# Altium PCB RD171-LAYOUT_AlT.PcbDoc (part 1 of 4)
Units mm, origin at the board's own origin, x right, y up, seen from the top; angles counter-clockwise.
Board outline 318.5 x 127 mm, 6 copper layers (TOP, Mid-Layer 1, Mid-Layer 2, Mid-Layer 3, Mid-Layer 4, BOTTOM), stack 1.422 mm thick; 473 components, 225 nets, 1188 pads, 1192 vias.
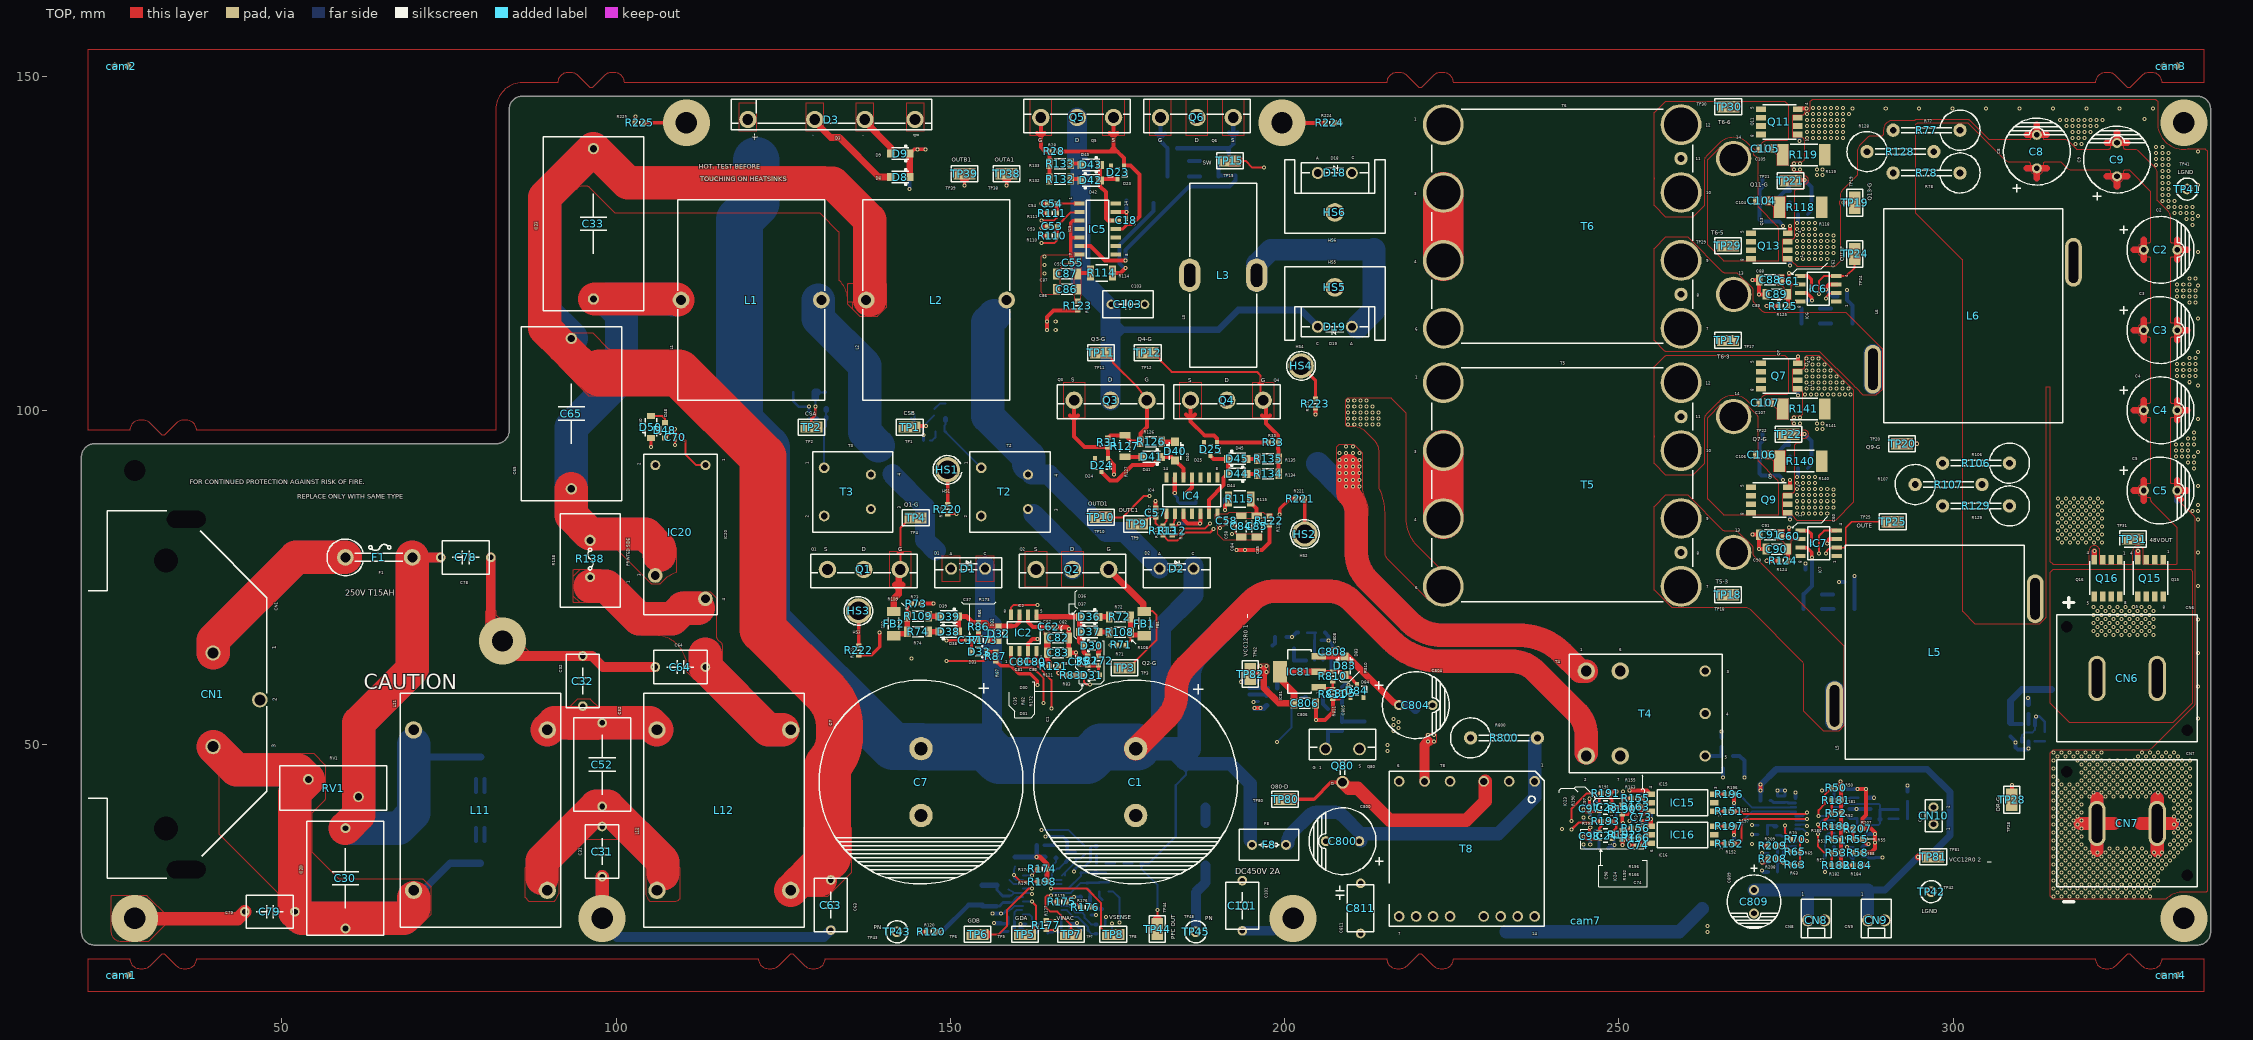
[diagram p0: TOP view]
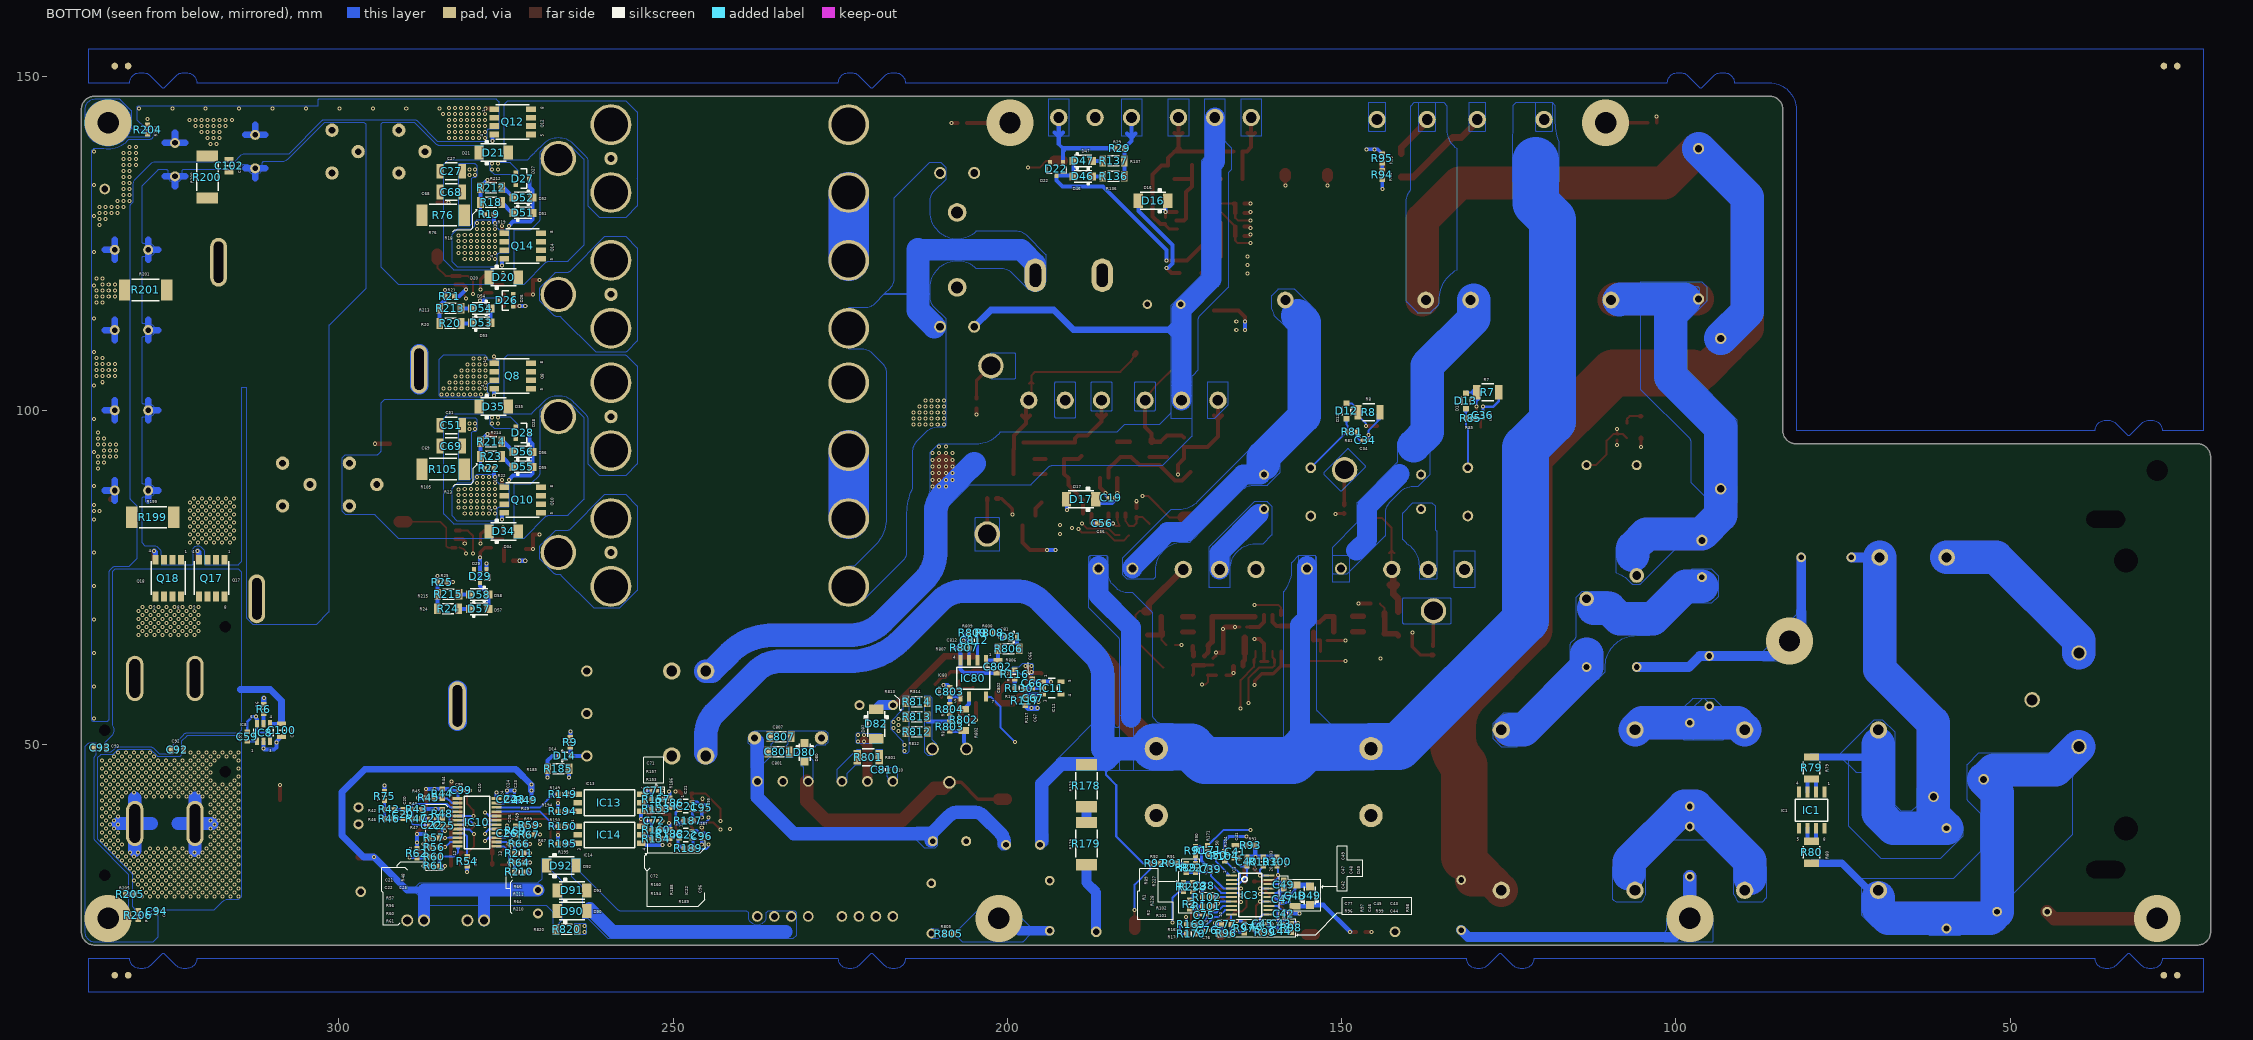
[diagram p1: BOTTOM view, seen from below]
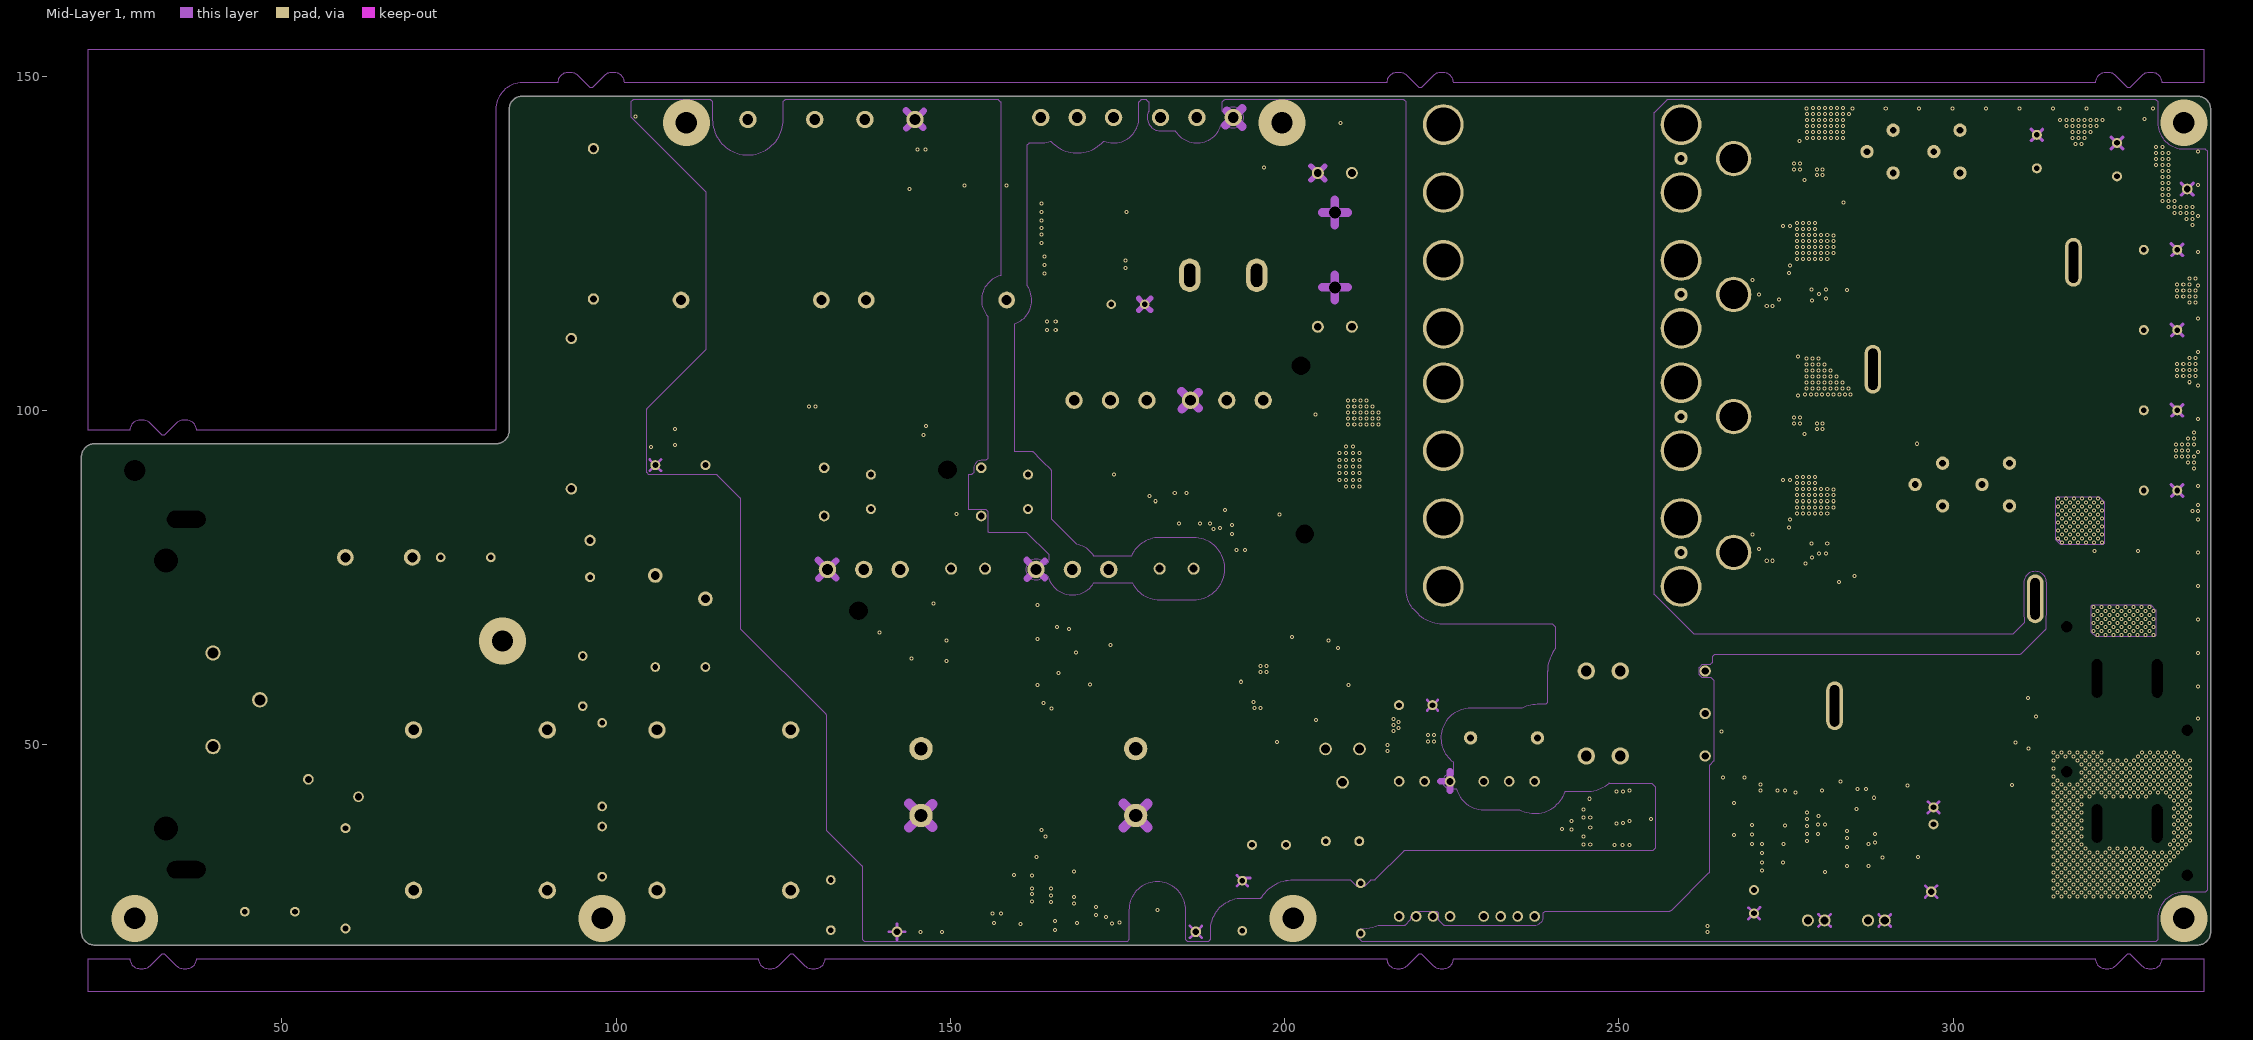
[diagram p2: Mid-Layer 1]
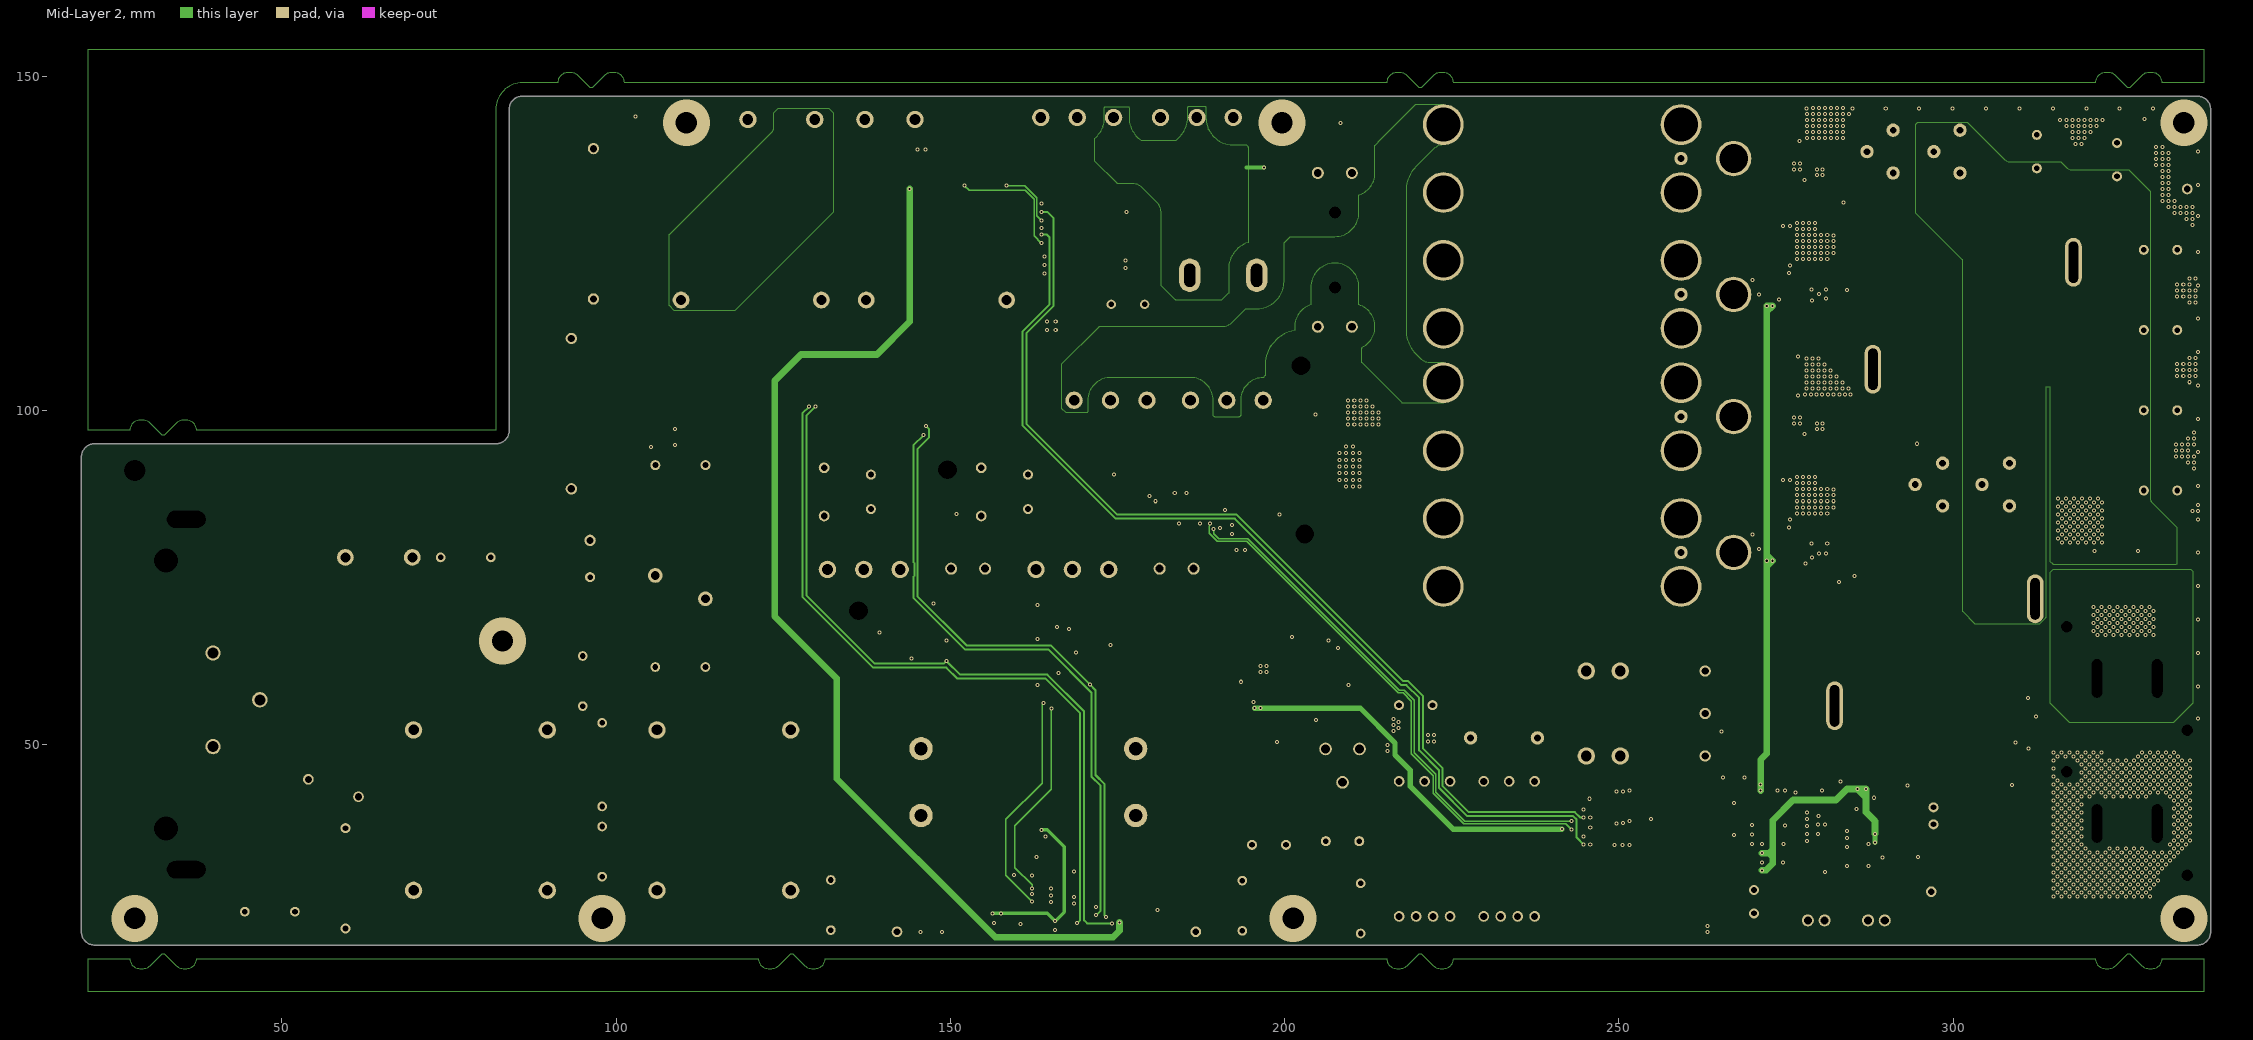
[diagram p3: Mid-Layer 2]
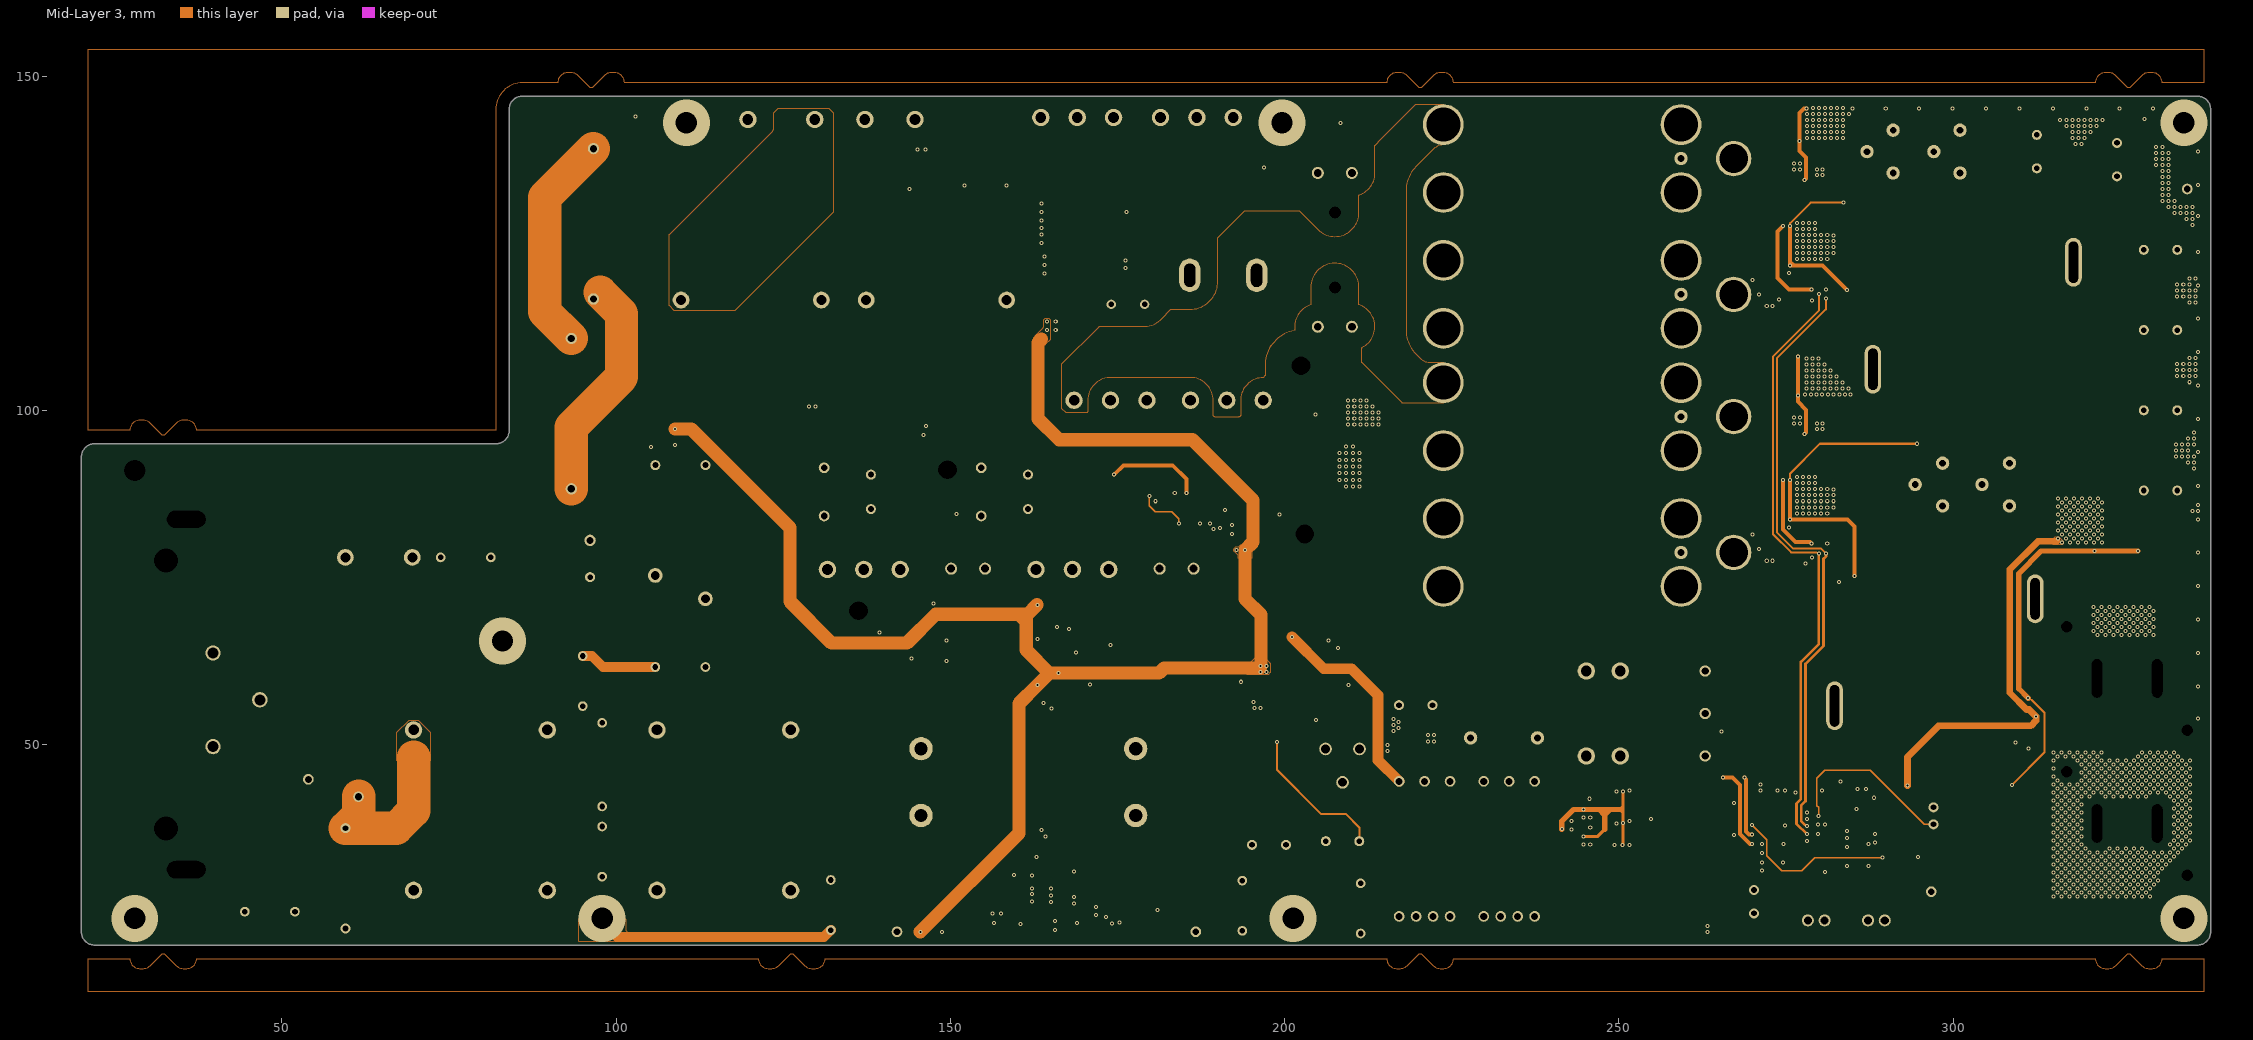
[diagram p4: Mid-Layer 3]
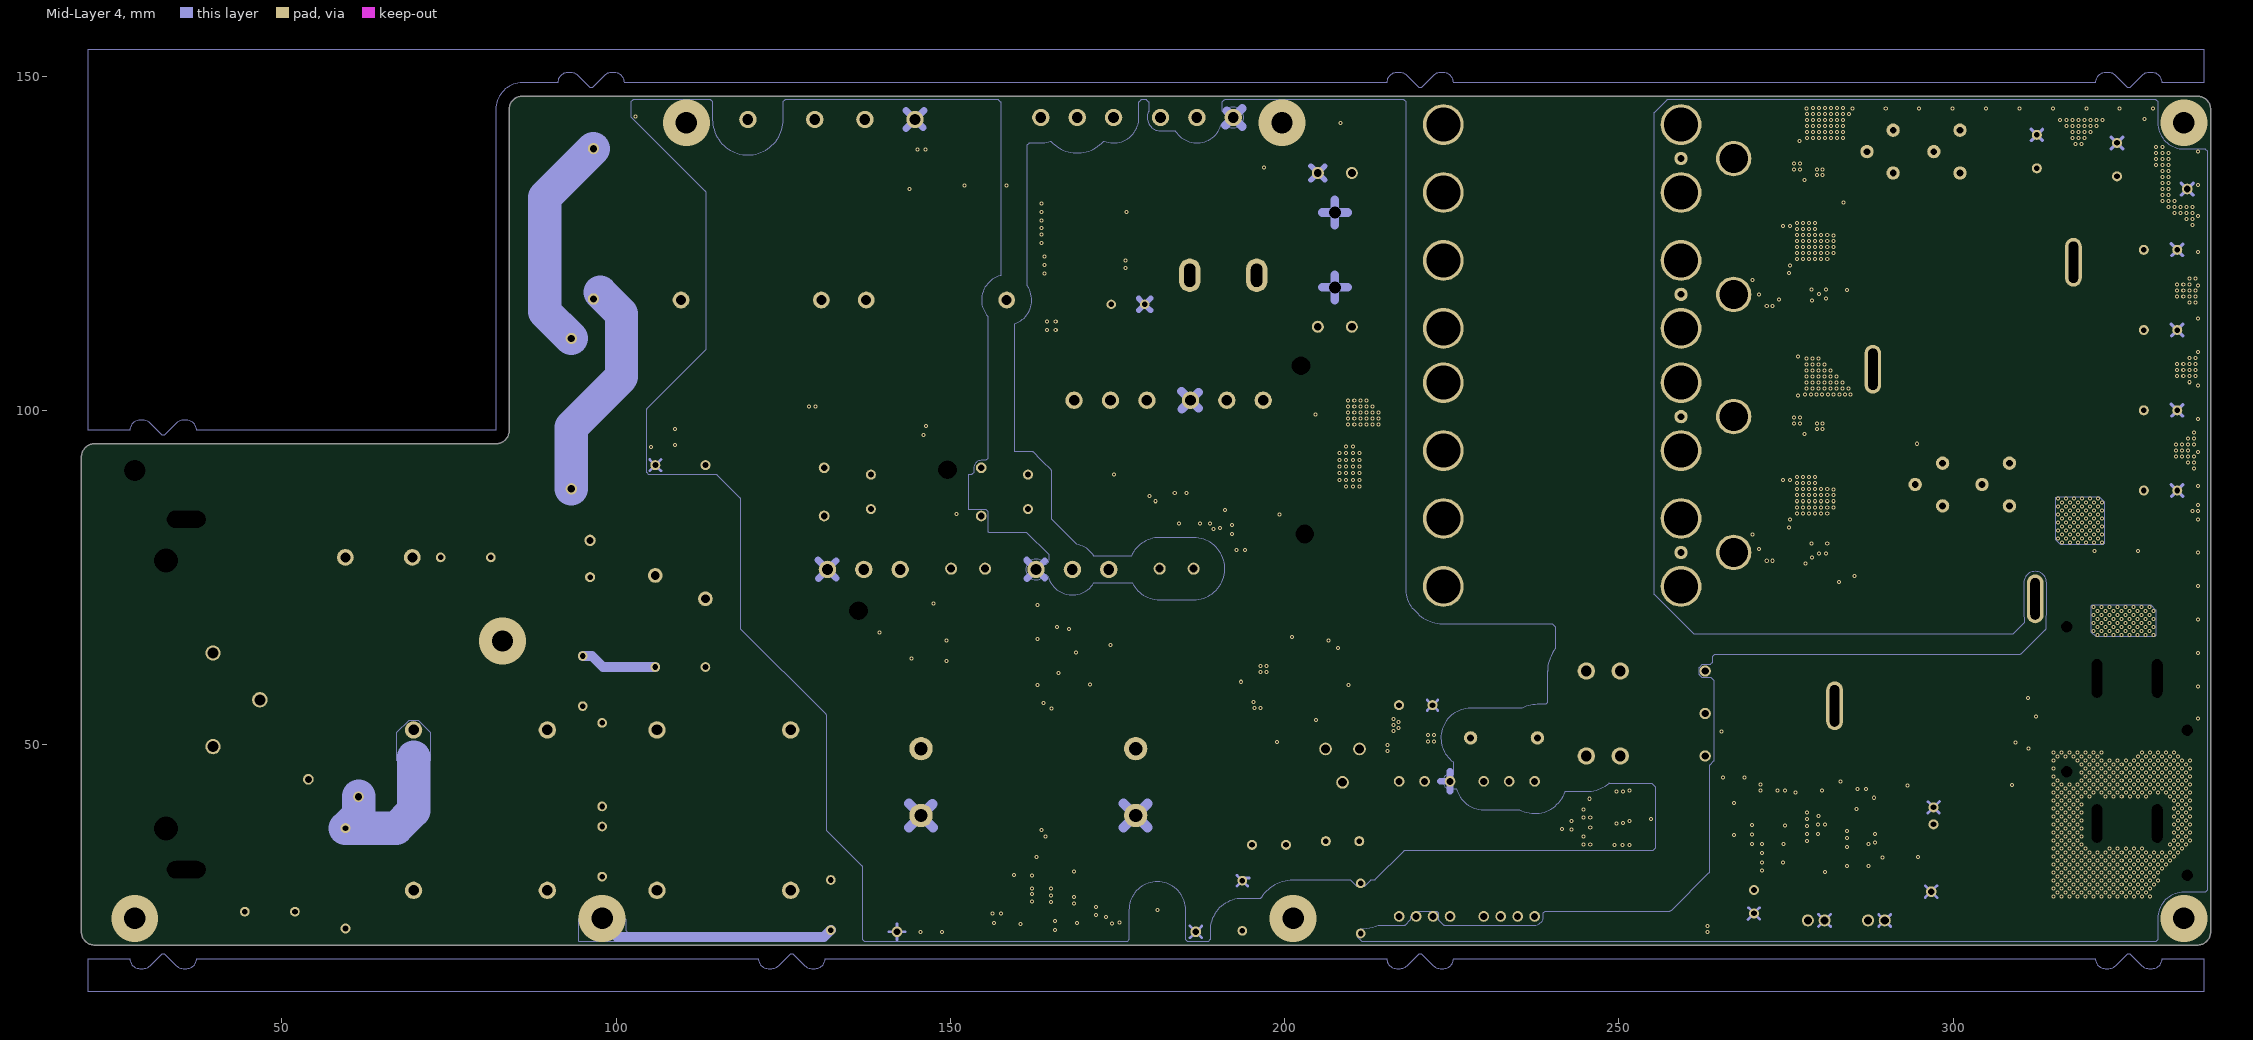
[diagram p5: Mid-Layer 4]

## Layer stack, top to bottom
Top Solder: solder mask 0.0102, Solder Resist, Dk 3.5
TOP: signal copper (thickness not stored)
Mid-Layer 1: signal copper 0.0356
Dielectric2: dielectric 0.32, FR-4, Dk 4.8
Mid-Layer 2: signal copper 0.0356
Dielectric3: dielectric 0.32, FR-4, Dk 4.8
Mid-Layer 3: signal copper 0.0356
Dielectric4: dielectric 0.32, FR-4, Dk 4.8
Mid-Layer 4: signal copper 0.0356
Dielectric5: dielectric 0.32, FR-4, Dk 4.8
BOTTOM: signal copper (thickness not stored)
Bottom Solder: solder mask 0.0102, Solder Resist, Dk 3.5

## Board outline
22,20 cw(c22,22) 20,22 20,93 cw(c22,93) 22,95 82,95 ccw(c82,97) 84,97 84,145 cw(c86,145) 86,147 336.5,147 cw(c336.5,145) 338.5,145 338.5,22 cw(c336.5,22) 336.5,20

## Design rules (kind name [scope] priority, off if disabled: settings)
AssemblyTestPointUsage [All] p0: scope1count=1 scope1_0_kind=Board scope1_0_value=Board scope2count=1 scope2_0_kind=Board scope2_0_value=Board commentlength=0
AssemblyTestpoint [All] p0: scope1count=1 scope1_0_kind=Board scope1_0_value=Board scope2count=1 scope2_0_kind=Board scope2_0_value=Board commentlength=0
Clearance [All] p0: scope1count=1 scope1_0_kind=Board scope1_0_value=Board scope2count=1 scope2_0_kind=Board scope2_0_value=Board commentlength=0 gap=0.001
Clearance [All] p1: gap=0.001 ignorepadtopadclearanceinfootprint=TRUE except(0.2: Arc-Arc Arc-Track Arc-SMDPad Arc-THPad Arc-Via Arc-Fill Arc-Poly Arc-Region Arc-Text Track-Track Track-SMDPad Track-THPad Track-Via Track-Fill Track-Poly Track-Region Track-Text SMDPad-SMDPad SMDPad-THPad SMDPad-Via SMDPad-Fill SMDPad-Poly SMDPad-Region SMDPad-Text THPad-THPad THPad-Via THPad-Fill THPad-Poly THPad-Region THPad-Text Via-Via Via-Fill Via-Poly Via-Region Via-Text Fill-Fill Fill-Poly Fill-Region Fill-Text Poly-Poly Poly-Region Poly-Text Region-Region Region-Text Text-Text; 0.49: Arc-Hole Track-Hole Fill-Hole Poly-Hole Region-Hole Text-Hole; 0.5: Via-Hole; 1: SMDPad-Hole THPad-Hole)
ComponentClearance [All] p0: scope1count=1 scope1_0_kind=Board scope1_0_value=Board scope2count=1 scope2_0_kind=Board scope2_0_value=Board commentlength=0 gap=0.254 collisioncheckmode=3
DiffPairsRouting [All] p0: scope1count=1 scope1_0_kind=Board scope1_0_value=Board scope2count=1 scope2_0_kind=Board scope2_0_value=Board commentlength=0
FabricationTestPointUsage [All] p0: scope1count=1 scope1_0_kind=Board scope1_0_value=Board scope2count=1 scope2_0_kind=Board scope2_0_value=Board commentlength=0 valid=0 allowmultiple=FALSE
FabricationTestpoint [All] p0: scope1count=1 scope1_0_kind=Board scope1_0_value=Board scope2count=1 scope2_0_kind=Board scope2_0_value=Board commentlength=0 side=3 testpointundercomponent=TRUE minsize=1.016 maxsize=2.54 preferedsize=1.524 minholesize=0 maxholesize=1.016 preferedholesize=0.813 testpointgrid=0.025
FanoutControl Fanout_Default [All] p0: scope1count=1 scope1_0_kind=Board scope1_0_value=Board scope2count=1 scope2_0_kind=Board scope2_0_value=Board commentlength=30 // Fanout_Default (Default Rule)
FanoutControl Fanout_Small [All] p0 off: scope1count=1 scope1_0_kind=Board scope1_0_value=Board scope2count=1 scope2_0_kind=Board scope2_0_value=Board commentlength=84 // Protel DXP Scope 1 Expression Was: (CompPinCount < 5)   Fanout_Small (Default Rule)
FanoutControl Fanout_SOIC [All] p0 off: scope1count=1 scope1_0_kind=Board scope1_0_value=Board scope2count=1 scope2_0_kind=Board scope2_0_value=Board commentlength=71 // Protel DXP Scope 1 Expression Was: IsSOIC   Fanout_SOIC (Default Rule)
FanoutControl Fanout_LCC [All] p0 off: scope1count=1 scope1_0_kind=Board scope1_0_value=Board scope2count=1 scope2_0_kind=Board scope2_0_value=Board commentlength=69 // Protel DXP Scope 1 Expression Was: IsLCC   Fanout_LCC (Default Rule)
FanoutControl Fanout_BGA [All] p0 off: scope1count=1 scope1_0_kind=Board scope1_0_value=Board scope2count=1 scope2_0_kind=Board scope2_0_value=Board commentlength=69 // Protel DXP Scope 1 Expression Was: IsBGA   Fanout_BGA (Default Rule)
Height [All] p0: scope1count=1 scope1_0_kind=Board scope1_0_value=Board scope2count=1 scope2_0_kind=Board scope2_0_value=Board commentlength=0
HoleSize [All] p0: scope1count=1 scope1_0_kind=Board scope1_0_value=Board scope2count=1 scope2_0_kind=Board scope2_0_value=Board commentlength=0 absolutevalues=TRUE maxlimit=100 minlimit=0.001 maxpercent=80.000 minpercent=20.000
HoleSize [All] p1: absolutevalues=TRUE maxlimit=100 minlimit=0.001 maxpercent=80.000 minpercent=20.000
HoleToHoleClearance [All] p0: scope1count=1 scope1_0_kind=Board scope1_0_value=Board scope2count=1 scope2_0_kind=Board scope2_0_value=Board commentlength=0
HoleToHoleClearance [All] p1: gap=0.5 allowstackedmicrovias=FALSE
LayerPairs [All] p0: scope1count=1 scope1_0_kind=Board scope1_0_value=Board scope2count=1 scope2_0_kind=Board scope2_0_value=Board commentlength=0 enforce=TRUE
MinimumSolderMaskSliver [All] p0: scope1count=1 scope1_0_kind=Board scope1_0_value=Board scope2count=1 scope2_0_kind=Board scope2_0_value=Board commentlength=0
MinimumSolderMaskSliver [All] p1: minsoldermaskwidth=0.1
NetAntennae [All] p0: scope1count=1 scope1_0_kind=Board scope1_0_value=Board scope2count=1 scope2_0_kind=Board scope2_0_value=Board commentlength=0
NetAntennae [All] p1: netantennaetolerance=100
PasteMaskExpansion [All] p0: scope1count=1 scope1_0_kind=Board scope1_0_value=Board scope2count=1 scope2_0_kind=Board scope2_0_value=Board commentlength=0 expansion=0
PlaneClearance [All] p0: scope1count=1 scope1_0_kind=Board scope1_0_value=Board scope2count=1 scope2_0_kind=Board scope2_0_value=Board commentlength=0 clearance=0.001
PlaneClearance [All] p1: clearance=0.001
PlaneConnect [All] p0: scope1count=1 scope1_0_kind=Board scope1_0_value=Board scope2count=1 scope2_0_kind=Board scope2_0_value=Board commentlength=0 planeconnectstyle=Direct reliefexpansion=0.508 reliefentries=4 reliefconductorwidth=0.254 reliefairgap=0.254
PlaneConnect [All] p1: planeconnectstyle=Direct reliefexpansion=0.508 reliefentries=4 reliefconductorwidth=0.254 reliefairgap=0.254
PolygonConnect [All] p0: scope1count=1 scope1_0_kind=Board scope1_0_value=Board scope2count=1 scope2_0_kind=Board scope2_0_value=Board commentlength=0 connectstyle=Direct reliefconductorwidth=0.254 reliefentries=4 polygonreliefangle="90 Angle"
PolygonConnect [All] p1: connectstyle=Direct reliefconductorwidth=0.254 reliefentries=4 polygonreliefangle="90 Angle" airgapwidth=0.254
RoutingCorners [All] p0: scope1count=1 scope1_0_kind=Board scope1_0_value=Board scope2count=1 scope2_0_kind=Board scope2_0_value=Board commentlength=0 cornerstyle=45-Degree minsetback=2.54 maxsetback=2.54
RoutingLayers [All] p0: scope1count=1 scope1_0_kind=Board scope1_0_value=Board scope2count=1 scope2_0_kind=Board scope2_0_value=Board commentlength=0 top layer=Automatic mid layer 1=Automatic mid layer 2=Automatic mid layer 3=Automatic mid layer 4=Automatic bottom layer=Automatic
RoutingPriority [All] p0: scope1count=1 scope1_0_kind=Board scope1_0_value=Board scope2count=1 scope2_0_kind=Board scope2_0_value=Board commentlength=0
RoutingTopology [All] p0: scope1count=1 scope1_0_kind=Board scope1_0_value=Board scope2count=1 scope2_0_kind=Board scope2_0_value=Board commentlength=0 topology=Shortest
RoutingVias [All] p0: scope1count=1 scope1_0_kind=Board scope1_0_value=Board scope2count=1 scope2_0_kind=Board scope2_0_value=Board commentlength=0 holewidth=0.1 width=0.1 viastyle="Through Hole" minholewidth=0.001 minwidth=0.001 maxholewidth=100 maxwidth=100
RoutingVias [All] p1: holewidth=0.1 width=0.1 viastyle="Through Hole" minholewidth=0.001 minwidth=0.001 maxholewidth=100 maxwidth=100
ShortCircuit [All] p0: scope1count=1 scope1_0_kind=Board scope1_0_value=Board scope2count=1 scope2_0_kind=Board scope2_0_value=Board commentlength=0 allowed=FALSE
SilkToBoardRegionClearance [All] p0: scope1count=1 scope1_0_kind=Board scope1_0_value=Board scope2count=1 scope2_0_kind=Board scope2_0_value=Board commentlength=0
SilkToSilkClearance [All] p0: scope1count=1 scope1_0_kind=Board scope1_0_value=Board scope2count=1 scope2_0_kind=Board scope2_0_value=Board commentlength=0
SilkToSilkClearance [All] p1: silktosilkclearance=0.001
SilkToSolderMaskClearance [All] p0 off: scope1count=1 scope1_0_kind=Board scope1_0_value=Board scope2count=1 scope2_0_kind=Board scope2_0_value=Board commentlength=44 // Protel DXP Scope 1 Expression Was: IsPad
SilkToSolderMaskClearance [IsPad] p1: minsilkscreentomaskgap=0.05 clearancetoexposedcopper=TRUE
SolderMaskExpansion [All] p0: scope1count=1 scope1_0_kind=Board scope1_0_value=Board scope2count=1 scope2_0_kind=Board scope2_0_value=Board commentlength=0 expansion=0.001
SolderMaskExpansion [All] p1: expansion=0.001
UnRoutedNet [All] p0: scope1count=1 scope1_0_kind=Board scope1_0_value=Board scope2count=1 scope2_0_kind=Board scope2_0_value=Board commentlength=0
UnpouredPolygon [All] p0: scope1count=1 scope1_0_kind=Board scope1_0_value=Board scope2count=1 scope2_0_kind=Board scope2_0_value=Board commentlength=0
Width [All] p0: scope1count=1 scope1_0_kind=Board scope1_0_value=Board scope2count=1 scope2_0_kind=Board scope2_0_value=Board commentlength=0 maxlimit=1000 minlimit=2539.975 preferedwidth=0
Width [All] p1: maxlimit=1000 minlimit=2539.975 preferedwidth=0 toplayer_minwidth=0 midlayer1_minwidth=0 midlayer2_minwidth=0 midlayer3_minwidth=0 midlayer4_minwidth=0 bottomlayer_minwidth=0 minimp=50.000000 maximp=50.000000 favimp=50.000000
22 further rules are at their usual default settings.

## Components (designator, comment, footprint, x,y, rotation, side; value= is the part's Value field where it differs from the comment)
C1 "AC_I_DIA-30_RB" AC_I_DIA-30_RB 177.7,44.4 r270 top
C2 "AC_I_DIA-10_CC" AC_I_DIA-10_CC 331,124 r0 top
C3 "AC_I_DIA-10_CC" AC_I_DIA-10_CC 331,112 r0 top
C4 "AC_I_DIA-10_CC" AC_I_DIA-10_CC 331,100 r0 top
C5 "AC_I_DIA-10_CC" AC_I_DIA-10_CC 331,88 r0 top
C7 "AC_I_DIA-30_RB" AC_I_DIA-30_RB 145.6,44.4 r270 top
C8 "AC_I_DIA-10_CC" AC_I_DIA-10_CC 312.5,138.7 r90 top
C9 "AC_I_DIA-10_CC" AC_I_DIA-10_CC 324.5,137.5 r90 top
C18 "Chip1005_GS_2" Chip1005_GS_2#1 176.3,128.4 r90 top
C19 "Chip1005_GS_2" Chip1005_GS_2#2 184.45,86.9 r0 bottom
C20 "Chip1608_GS_1" Chip1608_GS_1#1 290.35,39.6 r90 bottom
C21 "Chip1005_GS_2" Chip1005_GS_2#2 286.1,38.95 r0 bottom
C22 "Chip1005_GS_2" Chip1005_GS_2#2 286.1,37.95 r0 bottom
C23 "Chip1005_GS_2" Chip1005_GS_2#2 273.7,41.85 r90 bottom
C24 "Chip1005_GS_2" Chip1005_GS_2#2 274.8,41.85 r90 bottom
C25 "Chip1005_GS_2" Chip1005_GS_2#2 284.2,37.85 r0 bottom
C26 "Chip1005_GS_2" Chip1005_GS_2#2 274.8,36.75 r90 bottom
C27 "Chip3225_GS_1" Chip3225_GS_1#1 283.2,135.75 r180 bottom
C30 "C_I_LE474-M_OK" C_I_LE474-M_OK 59.5,30 r90 top
C31 "C_I_DE2**KY*******M**F_MU_2" C_I_DE2**KY*******M**F_MU_2 97.9,34 r90 top
C32 "C_I_DE2**KY*******M**F_MU_2" C_I_DE2**KY*******M**F_MU_2 95,59.5 r270 top
C33 "C_I_890324026034CS_WE" C_I_890324026034CS_WE 96.6,127.9 r270 top
C34 "Chip1005_GS_2" Chip1005_GS_2#2 146.45,95.5 r180 bottom
C35 "Chip1005_GS_2" Chip1005_GS_2#1 169.25,62.4 r270 top
C36 "Chip1005_GS_2" Chip1005_GS_2#2 128.85,99.25 r90 bottom
C37 "Chip1005_GS_2" Chip1005_GS_2#1 152.7,65.6 r0 top
C38 "Chip1005_GS_2" Chip1005_GS_2#2 170.55,28.85 r270 bottom
C39 "Chip1005_GS_2" Chip1005_GS_2#2 169.55,31.35 r90 bottom
C40 "Chip1608_GS_1" Chip1608_GS_1#1 164.15,32.5 r90 bottom
C41 "Chip2012_GS_1" Chip2012_GS_1#1 165.8,34 r90 bottom
C42 "Chip1005_GS_2" Chip1005_GS_2#2 158.65,24.7 r270 bottom
C43 "Chip1005_GS_2" Chip1005_GS_2#2 159.1,23.2 r180 bottom
C44 "Chip1005_GS_2" Chip1005_GS_2#2 159.1,22.1 r180 bottom
C45 "Chip1005_GS_2" Chip1005_GS_2#2 161.75,23.2 r180 bottom
C46 "Chip1005_GS_2" Chip1005_GS_2#2 163.25,22.75 r270 bottom
C47 "Chip1005_GS_2" Chip1005_GS_2#2 158.8,26.85 r90 bottom
C48 "Chip3216_GS_1" Chip3216_GS_1#1 156.95,27.4 r90 bottom
C49 "Chip1608_GS_1" Chip1608_GS_1#1 158.65,29.05 r270 bottom
C50 "Chip1005_GS_2" Chip1005_GS_2#2 168.75,33.45 r90 bottom
C51 "Chip3225_GS_1" Chip3225_GS_1#1 283.2,97.75 r180 bottom
C52 "C_I_LE224-M_OK" C_I_LE224-M_OK 97.9,47 r90 top
C53 "Chip1608_GS_1" Chip1608_GS_1#2 165.2,127.5 r0 top
C54 "Chip1608_GS_1" Chip1608_GS_1#2 165.2,130.9 r0 top
C55 "Chip1005_GS_2" Chip1005_GS_2#1 168.275,122.1 r0 top
C56 "Chip1608_GS_1" Chip1608_GS_1#1 185.8,83.1 r0 bottom
C57 "Chip1608_GS_1" Chip1608_GS_1#2 180.7,84.7 r270 top
C58 "Chip1005_GS_2" Chip1005_GS_2#1 191.3,83.5 r90 top
C59 "Chip1608_GS_1" Chip1608_GS_1#1 313.7,51.2 r270 bottom
C60 "Chip1005_GS_2" Chip1005_GS_2#1 275.45,81.2 r270 top
C61 "Chip1005_GS_2" Chip1005_GS_2#1 275.45,119.3 r270 top
C62 "Chip1005_GS_2" Chip1005_GS_2#1 164.7,67.6 r180 top
C63 "C_I_DE2**KY*******M**F_MU_2" C_I_DE2**KY*******M**F_MU_2 132.1,26 r90 top
C64 "C_I_DE2**KY*******M**F_MU_2" C_I_DE2**KY*******M**F_MU_2 109.6,61.6 r0 top
C65 "C_I_890324026034CS_WE" C_I_890324026034CS_WE 93.3,99.5 r270 top
C66 "Chip1608_GS_1" Chip1608_GS_1#1 196.25,59.15 r90 bottom
C67 "Chip1005_GS_2" Chip1005_GS_2#2 196.1,56.9 r270 bottom
C68 "Chip3225_GS_1" Chip3225_GS_1#1 283.2,132.65 r180 bottom
C69 "Chip3225_GS_1" Chip3225_GS_1#1 283.2,94.65 r180 bottom
C70 "Chip1005_GS_2" Chip1005_GS_2#1 108.8,96 r90 top
C71 "Chip1005_GS_2" Chip1005_GS_2#2 252.8,43.1 r180 bottom
C72 "Chip1005_GS_2" Chip1005_GS_2#2 252.8,38.6 r180 bottom
C73 "Chip1005_GS_2" Chip1005_GS_2#1 253.3,39.1 r90 top
C74 "Chip1005_GS_2" Chip1005_GS_2#1 252.85,34.95 r0 top
C75 "Chip1005_GS_2" Chip1005_GS_2#2 170.55,24.5 r0 bottom
C76 "Chip1005_GS_2" Chip1005_GS_2#2 170.1,22.2 r180 bottom
C77 "Chip1608_GS_1" Chip1608_GS_1#1 167.25,23.15 r0 bottom
C78 "C_I_DE2**KY*******M**F_MU" C_I_DE2**KY*******M**F_MU 77.5,78 r180 top
C79 "C_I_DE2**KY*******M**F_MU" C_I_DE2**KY*******M**F_MU 48.2,25 r0 top
C80 "Chip1005_GS_2" Chip1005_GS_2#1 162.65,62.4 r0 top
C81 "Chip1005_GS_2" Chip1005_GS_2#1 160.5,62.4 r180 top
C82 "Chip3216_GS_1" Chip3216_GS_1#2 166.1,65.95 r180 top
C83 "Chip3216_GS_1" Chip3216_GS_1#2 166.1,63.75 r180 top
C84 "Chip3216_GS_1" Chip3216_GS_1#2 193.5,82.65 r90 top
C85 "Chip3216_GS_1" Chip3216_GS_1#2 195.8,82.65 r90 top
C86 "Chip3216_GS_1" Chip3216_GS_1#2 167.425,118.1 r0 top
C87 "Chip3216_GS_1" Chip3216_GS_1#2 167.425,120.4 r0 top
C88 "Chip3216_GS_1" Chip3216_GS_1#2 272.6,119.5 r0 top
C89 "Chip3216_GS_1" Chip3216_GS_1#2 273.6,117.35 r0 top
C90 "Chip3216_GS_1" Chip3216_GS_1#2 273.6,79.25 r0 top
C91 "Chip3216_GS_1" Chip3216_GS_1#2 272.6,81.4 r0 top
C92 "Chip2012_GS_1" Chip2012_GS_1#1 324.15,49.25 r180 bottom
C93 "Chip2012_GS_1" Chip2012_GS_1#1 335.7,49.55 r0 bottom
C94 "Chip1005_GS_2" Chip1005_GS_2#2 327.25,25.05 r90 bottom
C95 "Chip1005_GS_2" Chip1005_GS_2#2 245.7,40.55 r270 bottom
C96 "Chip1005_GS_2" Chip1005_GS_2#2 245.7,36.3 r270 bottom
C97 "Chip1005_GS_2" Chip1005_GS_2#1 245.6,40.4 r270 top
C98 "Chip1005_GS_2" Chip1005_GS_2#1 245.6,36.3 r270 top
C99 "Chip1005_GS_2" Chip1005_GS_2#2 281.7,43.15 r180 bottom
C100 "Chip2012_GS_1" Chip2012_GS_1#1 308.55,52.15 r270 bottom
C101 "C_I_DE2**KY*******M**F_MU" C_I_DE2**KY*******M**F_MU 193.65,25.9 r270 top
C102 "Chip2012_GS_1" Chip2012_GS_1#1 316.4,136.6 r90 bottom
C103 "C_I_RDER72J104_MU" C_I_RDER72J104_MU 176.55,115.85 r180 top
C104 "Chip2012_GS_1" Chip2012_GS_1#2 271.35,131.35 r180 top
C105 "Chip2012_GS_1" Chip2012_GS_1#2 271.85,139.15 r180 top
C106 "Chip2012_GS_1" Chip2012_GS_1#2 271.35,93.35 r180 top
C107 "Chip2012_GS_1" Chip2012_GS_1#2 271.85,101.15 r180 top
C800 "AC_I_DIA-10_CC_2" AC_I_DIA-10_CC_2 208.65,35.55 r180 top
C801 "Chip3216_GS_1" Chip3216_GS_1#1 234.2,48.9 r0 bottom
C802 "Chip2012_GS_1" Chip2012_GS_1#1 201.4,61.65 r270 bottom
C803 "Chip1608_GS_1" Chip1608_GS_1#1 208.6,57.9 r90 bottom
C804 "AC_I_DIA-10_CC_3" AC_I_DIA-10_CC_3 219.6,55.9 r0 top
C805 "Chip1005_GS_2" Chip1005_GS_2#1 208.5,57.65 r270 top
C806 "Chip3216_GS_1" Chip3216_GS_1#2 203,56.2 r0 top
C807 "Chip3216_GS_1" Chip3216_GS_1#1 233.9,51.2 r0 bottom
C808 "Chip1005_GS_2" Chip1005_GS_2#1 207.15,63.925 r90 top
C809 "AC_I_DIA-8_CC_1" AC_I_DIA-8_CC_1 270.2,26.5 r270 top
C810 "Chip1005_GS_2" Chip1005_GS_2#2 218.25,46.25 r0 bottom
C811 "C_I_DE1B3RA471_GS_1" C_I_DE1B3RA471_GS_1 211.35,25.5 r90 top
C812 "Chip1005_GS_2" Chip1005_GS_2#2 204.95,65.6 r0 bottom
cam1 "FiducialMark_add_withM" FiducialMark_add_withM#1 25,15.5 r0 top
cam2 "FiducialMark_add_withM" FiducialMark_add_withM#1 25,151.5 r0 top
cam3 "FiducialMark_add_withM" FiducialMark_add_withM#2 321.5,151.5 r180 top
cam4 "FiducialMark_add_withM" FiducialMark_add_withM#2 321.5,15.5 r180 top
cam5 "PCB-Name_4x70" PCB-Name_4x70 150.6,-0.1 r0 top
cam6 "Drawing-Flame_4x120" Drawing-Flame_4x120 122.4,-5.8 r0 top
cam7 "Logo_TOSHIBA-A" Logo_TOSHIBA-A 245.05,23.65 r0 top
CN1 "TM_I_AC-P05CP24_ED" TM_I_AC-P05CP24_ED 23.9,57.5 r90 top
CN6 "TM_I_OP-910_GS" TM_I_OP-910_GS 326,59.9 r90 top
CN7 "TM_I_OP-910_GS" TM_I_OP-910_GS 326,38.2 r90 top
CN8 "CN_I_5045-02A_MX" CN_I_5045-02A_MX 279.5,23.7 r180 top
CN9 "CN_I_5045-02A_MX" CN_I_5045-02A_MX 288.5,23.7 r180 top
CN10 "HP_I_A2-2PA-2.54DSA_HR" HP_I_A2-2PA-2.54DSA_HR 297.05,39.35 r90 top
D1 "DI_I_TO220F-2L_TS" DI_I_TO220F-2L_TS 152.64,76.31 r180 top
D2 "DI_I_TO220F-2L_TS" DI_I_TO220F-2L_TS 183.84,76.31 r180 top
D3 "DI_I_GSIB-5S_4_VS" DI_I_GSIB-5S_4_VS 132.2,143.5 r0 top
D8 "DI_S_3-2A1S_2_TS_A" DI_S_3-2A1S_2_TS_A#1 142.5,134.9 r0 top
D9 "DI_S_3-2A1S_2_TS_A" DI_S_3-2A1S_2_TS_A#1 142.5,138.4 r0 top
D12 "DI_S_USC_2_TS_B" DI_S_USC_2_TS_B#1 149.25,99.9 r90 bottom
D13 "DI_S_USC_2_TS_B" DI_S_USC_2_TS_B#1 131.4,101.4 r90 bottom
D14 "DI_S_1SS387_TS_B" DI_S_1SS387_TS_B 266.2,48.3 r90 bottom
D16 "DI_S_3-4E1A_2_TS_B" DI_S_3-4E1A_2_TS_B 178.2,131.35 r0 bottom
D17 "DI_S_3-4E1A_2_TS_B" DI_S_3-4E1A_2_TS_B 188.95,86.7 r0 bottom
D18 "DI_I_TO220-2_KC" DI_I_TO220-2_KC 207.5,135.5 r180 top
D19 "DI_I_TO220-2_KC" DI_I_TO220-2_KC 207.5,112.5 r0 top
D20 "DI_S_3-4E1A_2_TS_B" DI_S_3-4E1A_2_TS_B 275.325,119.9 r180 bottom
D21 "DI_S_3-4E1A_2_TS_B" DI_S_3-4E1A_2_TS_B 276.825,138.55 r180 bottom
D22 "DI_S_SOT23_3_0.95_TS_B" DI_S_SOT23_3_0.95_TS_B#1 192.65,136.1 r180 bottom
D23 "DI_S_SOT23_3_0.95_TS_B" DI_S_SOT23_3_0.95_TS_B#2 175,135.6 r180 top
D24 "DI_S_SOT23_3_0.95_TS_B" DI_S_SOT23_3_0.95_TS_B#2 172.6,91.8 r180 top
D25 "DI_S_SOT23_3_0.95_TS_B" DI_S_SOT23_3_0.95_TS_B#2 188.9,94.2 r180 top
D26 "DI_S_SOT23_3_0.95_TS_B" DI_S_SOT23_3_0.95_TS_B#1 274.9,116.45 r270 bottom
D27 "DI_S_SOT23_3_0.95_TS_B" DI_S_SOT23_3_0.95_TS_B#1 272.5,134.65 r90 bottom
D28 "DI_S_SOT23_3_0.95_TS_B" DI_S_SOT23_3_0.95_TS_B#1 272.5,96.625 r90 bottom
D29 "DI_S_SOT23_3_0.95_TS_B" DI_S_SOT23_3_0.95_TS_B#1 278.85,75.2 r180 bottom
D30 "DI_S_USC_2_TS_B" DI_S_USC_2_TS_B#2 171.1,64.8 r0 top
D31 "DI_S_USC_2_TS_B" DI_S_USC_2_TS_B#2 171.15,60.35 r0 top
D32 "DI_S_USC_2_TS_B" DI_S_USC_2_TS_B#2 157.2,66.6 r270 top
D33 "DI_S_USC_2_TS_B" DI_S_USC_2_TS_B#2 154.3,63.9 r180 top
D34 "DI_S_3-4E1A_2_TS_B" DI_S_3-4E1A_2_TS_B 275.325,81.9 r180 bottom
D35 "DI_S_3-4E1A_2_TS_B" DI_S_3-4E1A_2_TS_B 276.825,100.55 r180 bottom
D36 "DI_S_CRS01_TS_B" DI_S_CRS01_TS_B#1 170.75,69.1 r0 top
D37 "DI_S_CRS01_TS_B" DI_S_CRS01_TS_B#1 170.75,66.85 r180 top
D38 "DI_S_CRS01_TS_B" DI_S_CRS01_TS_B#1 149.75,66.9 r180 top
D39 "DI_S_CRS01_TS_B" DI_S_CRS01_TS_B#1 149.75,69.15 r0 top
D40 "DI_S_CRS01_TS_B" DI_S_CRS01_TS_B#1 183.6,93.9 r90 top
D41 "DI_S_CRS01_TS_B" DI_S_CRS01_TS_B#1 180.1,93.05 r0 top
D42 "DI_S_CRS01_TS_B" DI_S_CRS01_TS_B#1 171,134.4 r180 top
D43 "DI_S_CRS01_TS_B" DI_S_CRS01_TS_B#1 171,136.7 r0 top
D44 "DI_S_CRS01_TS_B" DI_S_CRS01_TS_B#1 192.9,90.5 r0 top
D45 "DI_S_CRS01_TS_B" DI_S_CRS01_TS_B#1 192.9,92.75 r180 top
D46 "DI_S_CRS01_TS_B" DI_S_CRS01_TS_B#2 188.7,135 r0 bottom
D47 "DI_S_CRS01_TS_B" DI_S_CRS01_TS_B#2 188.7,137.3 r180 bottom
D48 "DI_S_USC_2_TS_B" DI_S_USC_2_TS_B#2 107.3,97 r90 top
D49 "DI_S_3-2A1S_2_TS_A" DI_S_3-2A1S_2_TS_A#2 154.75,27.4 r90 bottom
D50 "DI_S_SOD-123_2_OS_A" DI_S_SOD-123_2_OS_A 105.2,97.5 r270 top
D51 "DI_S_CRS01_TS_B" DI_S_CRS01_TS_B#2 272.45,129.55 r180 bottom
D52 "DI_S_CRS01_TS_B" DI_S_CRS01_TS_B#2 272.45,131.8 r0 bottom
D53 "DI_S_CRS01_TS_B" DI_S_CRS01_TS_B#2 278.7,113.1 r180 bottom
D54 "DI_S_CRS01_TS_B" DI_S_CRS01_TS_B#2 278.7,115.25 r0 bottom
D55 "DI_S_CRS01_TS_B" DI_S_CRS01_TS_B#2 272.45,91.55 r180 bottom
D56 "DI_S_CRS01_TS_B" DI_S_CRS01_TS_B#2 272.45,93.8 r0 bottom
D57 "DI_S_CRS01_TS_B" DI_S_CRS01_TS_B#2 279,70.3 r180 bottom
D58 "DI_S_CRS01_TS_B" DI_S_CRS01_TS_B#2 279,72.45 r0 bottom
D80 "DI_S_3-2A1S_2_TS_A" DI_S_3-2A1S_2_TS_A#2 230.3,48.85 r270 bottom
D81 "DI_S_1SS387_TS_B" DI_S_1SS387_TS_B 199.4,66.1 r270 bottom
D82 "DI_S_3-4E1A_2_TS_B" DI_S_3-4E1A_2_TS_B 219.6,53.1 r270 bottom
D83 "DI_S_CRS01_TS_B" DI_S_CRS01_TS_B#1 208.95,61.8 r90 top
D84 "DI_S_SOT23_3_0.95_TS_B" DI_S_SOT23_3_0.95_TS_B#2 210.8,58.05 r0 top
D90 "DI_S_3-4E1A_2_TS_B" DI_S_3-4E1A_2_TS_B 265.1,25.1 r180 bottom
D91 "DI_S_3-4E1A_2_TS_B" DI_S_3-4E1A_2_TS_B 265.1,28.2 r180 bottom
D92 "DI_S_3-4E1A_2_TS_B" DI_S_3-4E1A_2_TS_B 266.7,31.9 r180 bottom
F1 "F_I_02150***XEP_LF" F_I_02150***XEP_LF 59.5,78 r0 top
F8 "F_I_808****0440_LF" F_I_808****0440_LF 197.65,35 r0 top
FB1 "FB_S_FBMH3216_TY" FB_S_FBMH3216_TY 179,68.1 r90 top
FB2 "FB_S_FBMH3216_TY" FB_S_FBMH3216_TY 141.5,68.1 r90 top
HS1 "TP_I_TH2.8_TBLC3.8_ILC0_RC3.9_GS" TP_I_TH2.8_TBLC3.8_ILC0_RC3.9_GS 149.55,91.1 r0 top
HS2 "TP_I_TH2.8_TBLC3.8_ILC0_RC3.9_GS" TP_I_TH2.8_TBLC3.8_ILC0_RC3.9_GS 203,81.5 r0 top
HS3 "TP_I_TH2.8_TBLC3.8_ILC0_RC3.9_GS" TP_I_TH2.8_TBLC3.8_ILC0_RC3.9_GS 136.25,70 r0 top
HS4 "TP_I_TH2.8_TBLC3.8_ILC0_RC3.9_GS" TP_I_TH2.8_TBLC3.8_ILC0_RC3.9_GS 202.45,106.65 r0 top
HS5 "HS_I_BPUS15-25_GS" HS_I_BPUS15-25_GS 207.5,115.5 r0 top
HS6 "HS_I_BPUS15-25_GS" HS_I_BPUS15-25_GS 207.5,132.5 r180 top
IC1 "IC_S_SOP_8_1.27_MPS" IC_S_SOP_8_1.27_MPS 79.7,40.2 r180 bottom
IC2 "IC_S_SOP_8_1.27_TI" IC_S_SOP_8_1.27_TI 160.95,66.7 r0 top
IC3 "IC_S_SOP_20_0.65_TI" IC_S_SOP_20_0.65_TI 163.65,27.5 r90 bottom
IC4 "IC_S_SOP_14_1.27_TI" IC_S_SOP_14_1.27_TI 186.1,87.25 r0 top
IC5 "IC_S_SOP_14_1.27_TI" IC_S_SOP_14_1.27_TI 172,127.1 r270 top
IC6 "IC_S_SOP_8_1.27_TI" IC_S_SOP_8_1.27_TI 279.8,118.2 r90 top
IC7 "IC_S_SOP_8_1.27_TI" IC_S_SOP_8_1.27_TI 279.85,80.1 r90 top
IC8 "IC_S_SOP_6_0.95_TI" IC_S_SOP_6_0.95_TI 311.25,51.8 r0 bottom
IC10 "IC_S_SOP_24_0.65_GS_1" IC_S_SOP_24_0.65_GS_1 279.3,38.35 r90 bottom
IC11 "IC_S_SOP_5_0.95_TI" IC_S_SOP_5_0.95_TI 193.35,58.45 r90 bottom
IC13 "PH_S_TLP2767_TS" PH_S_TLP2767_TS#1 259.5,41.3 r90 bottom
IC14 "PH_S_TLP2767_TS" PH_S_TLP2767_TS#1 259.5,36.5 r90 bottom
IC15 "PH_S_TLP2767_TS" PH_S_TLP2767_TS#2 259.5,41.3 r90 top
IC16 "PH_S_TLP2767_TS" PH_S_TLP2767_TS#2 259.5,36.5 r90 top
IC20 "RE_I_ALKG*2**_PN" RE_I_ALKG*2**_PN 109.6,81.45 r270 top
IC21 "IC_S_SOP_5_0.65_TS_1" IC_S_SOP_5_0.65_TS_1#1 248.1,40.8 r90 bottom
IC22 "IC_S_SOP_5_0.65_TS_1" IC_S_SOP_5_0.65_TS_1#1 248.1,36.5 r90 bottom
IC23 "IC_S_SOP_5_0.65_TS_1" IC_S_SOP_5_0.65_TS_1#2 248,40.6 r90 top
IC24 "IC_S_SOP_5_0.65_TS_1" IC_S_SOP_5_0.65_TS_1#2 248,36.4 r90 top
IC80 "IC_S_SOP_7_1.27_TI" IC_S_SOP_7_1.27_TI 205.1,59.9 r180 bottom
IC81 "IC_S_SOT223_3_2.3_TI" IC_S_SOT223_3_2.3_TI 205.1,60.9 r90 top
L1 "L_I_TH23/14V-08231_TP" L_I_TH23/14V-08231_TP 120.2,116.5 r270 top
L2 "L_I_TH23/14V-08231_TP" L_I_TH23/14V-08231_TP 147.9,116.5 r270 top
L3 "L_I_NPA080-13x2-20T_GS" L_I_NPA080-13x2-20T_GS 190.8,120.2 r270 top
L5 "L_I_AG1391_GS" L_I_AG1391_GS 297.25,63.8 r270 top
L6 "L_I_AG1391_GS" L_I_AG1391_GS 302.975,114.15 r270 top
L11 "L_I_SCF27-10-1300_TN" L_I_SCF27-10-1300_TN 79.7,40.2 r270 top
L12 "L_I_SCF27-10-1300_TN" L_I_SCF27-10-1300_TN 116.1,40.2 r270 top
Q1 "TR_I_TO247_3_TS" TR_I_TO247_3_TS 137.04,76.2 r180 top
Q2 "TR_I_TO247_3_TS" TR_I_TO247_3_TS 168.24,76.2 r180 top
Q3 "TR_I_TO247_3_TS" TR_I_TO247_3_TS 173.94,101.5 r180 top
Q4 "TR_I_TO247_3_TS" TR_I_TO247_3_TS 191.34,101.5 r180 top
Q5 "TR_I_TO247_3_TS" TR_I_TO247_3_TS 168.96,143.8 r0 top
Q6 "TR_I_TO247_3_TS" TR_I_TO247_3_TS 186.86,143.8 r0 top
Q7 "TR_S_SOP-ADVANCE_TS" TR_S_SOP-ADVANCE_TS#1 274,105.15 r90 top
Q8 "TR_S_SOP-ADVANCE_TS" TR_S_SOP-ADVANCE_TS#2 274,105.15 r90 bottom
Q9 "TR_S_SOP-ADVANCE_TS" TR_S_SOP-ADVANCE_TS#1 272.5,86.6 r90 top
Q10 "TR_S_SOP-ADVANCE_TS" TR_S_SOP-ADVANCE_TS#2 272.5,86.6 r90 bottom
Q11 "TR_S_SOP-ADVANCE_TS" TR_S_SOP-ADVANCE_TS#1 274,143.15 r90 top
Q12 "TR_S_SOP-ADVANCE_TS" TR_S_SOP-ADVANCE_TS#2 274,143.15 r90 bottom
Q13 "TR_S_SOP-ADVANCE_TS" TR_S_SOP-ADVANCE_TS#1 272.5,124.6 r90 top
Q14 "TR_S_SOP-ADVANCE_TS" TR_S_SOP-ADVANCE_TS#2 272.5,124.6 r90 bottom
Q15 "TR_S_SOP-ADVANCE_TS" TR_S_SOP-ADVANCE_TS#1 329.5,74.9 r180 top
Q16 "TR_S_SOP-ADVANCE_TS" TR_S_SOP-ADVANCE_TS#1 323,74.9 r180 top
Q17 "TR_S_SOP-ADVANCE_TS" TR_S_SOP-ADVANCE_TS#2 319,74.9 r180 bottom
Q18 "TR_S_SOP-ADVANCE_TS" TR_S_SOP-ADVANCE_TS#2 325.5,74.9 r180 bottom
Q80 "TR_I_TO220SIS_TS_1" TR_I_TO220SIS_TS_1 208.65,49.35 r0 top
R1 "Chip1608_GS_1" Chip1608_GS_1#1 173.65,28.7 r90 bottom
R2 "Chip1608_GS_1" Chip1608_GS_1#1 172.7,26.1 r270 bottom
R6 "Chip1608_GS_1" Chip1608_GS_1#1 311.2,55.3 r270 bottom
R7 "Chip3225_GS_1" Chip3225_GS_1#1 128.15,102.7 r180 bottom
R8 "Chip3225_GS_1" Chip3225_GS_1#1 145.9,99.7 r180 bottom
R9 "Chip1608_GS_1" Chip1608_GS_1#1 265.35,50.35 r90 bottom
R18 "Chip3216_GS_1" Chip3216_GS_1#1 277.2,131.1 r180 bottom
R19 "Chip1608_GS_1" Chip1608_GS_1#1 277.5,129.3 r180 bottom
R20 "Chip3216_GS_1" Chip3216_GS_1#1 283.3,113 r180 bottom
R21 "Chip1608_GS_1" Chip1608_GS_1#1 283.4,117.05 r180 bottom
R22 "Chip1608_GS_1" Chip1608_GS_1#1 277.5,91.3 r180 bottom
R23 "Chip3216_GS_1" Chip3216_GS_1#1 277.2,93.1 r180 bottom
R24 "Chip3216_GS_1" Chip3216_GS_1#1 283.65,70.3 r180 bottom
R25 "Chip1608_GS_1" Chip1608_GS_1#1 284.5,74.3 r180 bottom
R28 "Chip1608_GS_1" Chip1608_GS_1#2 165.5,138.75 r180 top
R29 "Chip1608_GS_1" Chip1608_GS_1#1 183.2,139.2 r0 bottom
R31 "Chip1608_GS_1" Chip1608_GS_1#2 173.55,95.2 r90 top
R33 "Chip1608_GS_1" Chip1608_GS_1#2 198.3,95.2 r0 top
R42 "Chip1608_GS_1" Chip1608_GS_1#1 292.45,40.3 r180 bottom
R43 "Chip1608_GS_1" Chip1608_GS_1#1 288.35,40.3 r180 bottom
R44 "Chip1608_GS_1" Chip1608_GS_1#1 284.5,42.65 r270 bottom
R45 "Chip1608_GS_1" Chip1608_GS_1#1 286.5,42.05 r0 bottom
R46 "Chip1608_GS_1" Chip1608_GS_1#1 292.45,38.9 r180 bottom
R47 "Chip1608_GS_1" Chip1608_GS_1#1 288.35,38.9 r180 bottom
R48 "Chip1608_GS_1" Chip1608_GS_1#1 284.5,39.65 r90 bottom
R49 "Chip1608_GS_1" Chip1608_GS_1#1 271.9,41.65 r180 bottom
R50 "Chip1608_GS_1" Chip1608_GS_1#2 282.5,43.55 r180 top
R51 "Chip1608_GS_1" Chip1608_GS_1#2 282.5,35.75 r180 top
R52 "Chip1608_GS_1" Chip1608_GS_1#2 282.5,39.75 r180 top
R53 "Chip1608_GS_1" Chip1608_GS_1#2 282.5,33.85 r180 top
R54 "Chip1608_GS_1" Chip1608_GS_1#1 280.8,32.55 r270 bottom
R55 "Chip1608_GS_1" Chip1608_GS_1#2 285.7,35.85 r180 top
R56 "Chip1608_GS_1" Chip1608_GS_1#1 285.7,34.65 r0 bottom
R57 "Chip1608_GS_1" Chip1608_GS_1#1 285.7,36.05 r180 bottom
R58 "Chip1608_GS_1" Chip1608_GS_1#2 285.7,33.85 r0 top
R59 "Chip1608_GS_1" Chip1608_GS_1#1 271.5,37.95 r180 bottom
R60 "Chip1608_GS_1" Chip1608_GS_1#1 285.7,33.25 r180 bottom
R61 "Chip1608_GS_1" Chip1608_GS_1#1 285.7,31.85 r0 bottom
R62 "Chip1608_GS_1" Chip1608_GS_1#1 288.3,33.75 r270 bottom
R63 "Chip1608_GS_1" Chip1608_GS_1#2 276.4,32.05 r0 top
R64 "Chip1608_GS_1" Chip1608_GS_1#1 273,32.35 r180 bottom
R65 "Chip1608_GS_1" Chip1608_GS_1#2 276.4,33.95 r0 top
R66 "Chip1608_GS_1" Chip1608_GS_1#1 273,35.15 r180 bottom
R67 "Chip1608_GS_1" Chip1608_GS_1#1 271.5,36.55 r0 bottom
R69 "Chip1608_GS_1" Chip1608_GS_1#1 273.5,37.15 r270 bottom
R70 "Chip1608_GS_1" Chip1608_GS_1#2 276.4,35.85 r0 top
R71 "Chip1608_GS_1" Chip1608_GS_1#2 175.55,64.9 r0 top
R72 "Chip3216_GS_1" Chip3216_GS_1#2 175.35,69.1 r0 top
R73 "Chip1608_GS_1" Chip1608_GS_1#2 144.9,71.1 r180 top
R74 "Chip3216_GS_1" Chip3216_GS_1#2 145.15,66.9 r180 top
R75 "Chip1608_GS_1" Chip1608_GS_1#1 293.15,42.3 r270 bottom
R76 "Chip6432_GS" Chip6432_GS#1 284.4,129.2 r180 bottom
R77 "R_I_MOS3C_KO" R_I_MOS3C_KO 301,141.9 r180 top
R78 "R_I_MOS3C_KO" R_I_MOS3C_KO 301,135.5 r180 top
R79 "Chip3225_GS_1" Chip3225_GS_1#1 79.7,46.5 r270 bottom
R80 "Chip3225_GS_1" Chip3225_GS_1#1 79.7,33.9 r270 bottom
R81 "Chip1608_GS_1" Chip1608_GS_1#1 148.4,96.8 r180 bottom
R82 "Chip1608_GS_1" Chip1608_GS_1#2 170.55,62.55 r270 top
R83 "Chip1608_GS_1" Chip1608_GS_1#2 168,60.35 r180 top
R85 "Chip1608_GS_1" Chip1608_GS_1#1 130.7,98.8 r180 bottom
R86 "Chip1608_GS_1" Chip1608_GS_1#2 154.2,67.6 r270 top
R87 "Chip1608_GS_1" Chip1608_GS_1#2 156.8,63.2 r270 top
R89 "Chip1608_GS_1" Chip1608_GS_1#1 173.25,31.55 r270 bottom
R90 "Chip1608_GS_1" Chip1608_GS_1#1 171.85,34.1 r90 bottom
R91 "Chip1608_GS_1" Chip1608_GS_1#1 175.25,32.25 r180 bottom
R92 "Chip1608_GS_1" Chip1608_GS_1#1 177.85,32.25 r180 bottom
R93 "Chip1608_GS_1" Chip1608_GS_1#1 163.6,34.95 r180 bottom
R94 "Chip1608_GS_1" Chip1608_GS_1#1 143.9,135.2 r270 bottom
R95 "Chip1608_GS_1" Chip1608_GS_1#1 143.9,137.7 r270 bottom
R96 "Chip1608_GS_1" Chip1608_GS_1#1 167.25,21.8 r0 bottom
R97 "Chip1608_GS_1" Chip1608_GS_1#1 164.55,22.5 r270 bottom
R98 "Chip1608_GS_1" Chip1608_GS_1#1 157.5,22.6 r90 bottom
R99 "Chip1608_GS_1" Chip1608_GS_1#1 161.45,21.9 r180 bottom
R100 "Chip1608_GS_1" Chip1608_GS_1#1 159.65,32.5 r90 bottom
R101 "Chip1608_GS_1" Chip1608_GS_1#1 170.15,25.8 r0 bottom
R102 "Chip1608_GS_1" Chip1608_GS_1#1 170.15,27.2 r0 bottom
R103 "Chip1608_GS_1" Chip1608_GS_1#1 161.7,32.5 r90 bottom
R104 "Chip1608_GS_1" Chip1608_GS_1#1 167.45,33.3 r90 bottom
R105 "Chip6432_GS" Chip6432_GS#1 284.4,91.2 r180 bottom
R106 "R_I_MOS3C_KO" R_I_MOS3C_KO 308.4,92.1 r180 top
R107 "R_I_MOS3C_KO" R_I_MOS3C_KO 294.3,88.9 r0 top
R108 "Chip3216_GS_1" Chip3216_GS_1#2 175.35,66.8 r0 top
R109 "Chip3216_GS_1" Chip3216_GS_1#2 145.15,69.2 r180 top
R110 "Chip1608_GS_1" Chip1608_GS_1#2 165.2,126.1 r0 top
R111 "Chip1608_GS_1" Chip1608_GS_1#2 165.2,129.5 r0 top
R112 "Chip1608_GS_1" Chip1608_GS_1#2 183.2,82 r90 top
R113 "Chip1608_GS_1" Chip1608_GS_1#2 181.8,82 r90 top
R114 "Chip3225_GS_1" Chip3225_GS_1#2 172.6,120.55 r0 top
R115 "Chip3225_GS_1" Chip3225_GS_1#2 193.25,86.75 r180 top
R116 "Chip1608_GS_1" Chip1608_GS_1#1 198.9,60.5 r90 bottom
R117 "Chip1608_GS_1" Chip1608_GS_1#1 197.3,56.55 r90 bottom
R118 "Chip6432_GS" Chip6432_GS#2 277.15,130.4 r180 top
R119 "Chip6432_GS" Chip6432_GS#2 277.65,138.2 r180 top
R120 "Chip1608_GS_1" Chip1608_GS_1#2 147.1,22 r0 top
R121 "Chip1608_GS_1" Chip1608_GS_1#2 165.45,61.7 r180 top
R122 "Chip1608_GS_1" Chip1608_GS_1#2 197.7,83.5 r90 top
R123 "Chip1608_GS_1" Chip1608_GS_1#2 169.025,115.65 r90 top
R124 "Chip1608_GS_1" Chip1608_GS_1#2 274.6,77.5 r0 top
R125 "Chip1608_GS_1" Chip1608_GS_1#2 274.6,115.6 r0 top
R126 "Chip3216_GS_1" Chip3216_GS_1#2 180,95.3 r180 top
R127 "Chip3216_GS_1" Chip3216_GS_1#2 176.1,94.65 r90 top
R128 "R_I_MOS3C_KO" R_I_MOS3C_KO 287.1,138.7 r0 top
R129 "R_I_MOS3C_KO" R_I_MOS3C_KO 308.4,85.7 r180 top
R130 "Chip1608_GS_1" Chip1608_GS_1#1 198.2,58.45 r0 bottom
R132 "Chip3216_GS_1" Chip3216_GS_1#2 166.4,134.6 r180 top
R133 "Chip3216_GS_1" Chip3216_GS_1#2 166.4,136.9 r180 top
R134 "Chip3216_GS_1" Chip3216_GS_1#2 197.5,90.5 r0 top
R135 "Chip3216_GS_1" Chip3216_GS_1#2 197.5,92.75 r0 top
R136 "Chip3216_GS_1" Chip3216_GS_1#1 184.1,135 r0 bottom
R137 "Chip3216_GS_1" Chip3216_GS_1#1 184.1,137.3 r0 bottom
R138 "F_I_A5MC_UC" F_I_A5MC_UC 96.1,77.8 r90 top
R140 "Chip6432_GS" Chip6432_GS#2 277.15,92.4 r180 top
R141 "Chip6432_GS" Chip6432_GS#2 277.65,100.2 r180 top
R149 "Chip1608_GS_1" Chip1608_GS_1#1 266.5,42.55 r180 bottom
R150 "Chip1608_GS_1" Chip1608_GS_1#1 266.5,37.8 r180 bottom
R151 "Chip1608_GS_1" Chip1608_GS_1#2 266.5,40 r0 top
R152 "Chip1608_GS_1" Chip1608_GS_1#2 266.5,35.2 r0 top
R153 "Chip1608_GS_1" Chip1608_GS_1#1 252.5,40.4 r180 bottom
R154 "Chip1608_GS_1" Chip1608_GS_1#1 252.5,35.9 r180 bottom
R155 "Chip1608_GS_1" Chip1608_GS_1#2 252.5,42 r0 top
R156 "Chip1608_GS_1" Chip1608_GS_1#2 252.5,37.5 r0 top
R157 "Chip1608_GS_1" Chip1608_GS_1#1 252.5,41.8 r180 bottom
R160 "Chip1608_GS_1" Chip1608_GS_1#1 252.5,37.3 r180 bottom
R163 "Chip1608_GS_1" Chip1608_GS_1#2 252.5,40.7 r0 top
R166 "Chip1608_GS_1" Chip1608_GS_1#2 252.5,36.1 r0 top
R169 "Chip1608_GS_1" Chip1608_GS_1#1 172.5,23.1 r0 bottom
R170 "Chip1608_GS_1" Chip1608_GS_1#1 172.5,21.7 r0 bottom
R171 "Chip1608_GS_1" Chip1608_GS_1#1 170.05,34.2 r270 bottom
R172 "Chip1608_GS_1" Chip1608_GS_1#2 172.15,62.55 r270 top
R173 "Chip1608_GS_1" Chip1608_GS_1#2 154.9,65.6 r180 top
R174 "Chip1608_GS_1" Chip1608_GS_1#2 163.75,31.4 r180 top
R175 "Chip1608_GS_1" Chip1608_GS_1#2 166.65,26.5 r0 top
R176 "Chip1608_GS_1" Chip1608_GS_1#2 170.15,25.7 r180 top
R177 "Chip1608_GS_1" Chip1608_GS_1#2 164.35,23 r90 top
R178 "Chip6432_GS" Chip6432_GS#1 188.15,43.85 r270 bottom
R179 "Chip6432_GS" Chip6432_GS#1 188.15,35.2 r270 bottom
R180 "Chip1608_GS_1" Chip1608_GS_1#2 282.5,37.75 r180 top
R181 "Chip1608_GS_1" Chip1608_GS_1#2 282.5,41.65 r180 top
R182 "Chip1608_GS_1" Chip1608_GS_1#2 282.5,31.95 r180 top
R184 "Chip1608_GS_1" Chip1608_GS_1#2 285.7,31.95 r180 top
R185 "Chip3216_GS_1" Chip3216_GS_1#1 267.15,46.4 r180 bottom
R186 "Chip1608_GS_1" Chip1608_GS_1#1 250.5,41.3 r270 bottom
R187 "Chip1608_GS_1" Chip1608_GS_1#1 247.7,38.6 r0 bottom
R188 "Chip1608_GS_1" Chip1608_GS_1#1 250.5,36.65 r270 bottom
R189 "Chip1608_GS_1" Chip1608_GS_1#1 247.7,34.5 r0 bottom
R190 "Chip1608_GS_1" Chip1608_GS_1#2 250.5,40.3 r270 top
R191 "Chip1608_GS_1" Chip1608_GS_1#2 248,42.7 r180 top
R192 "Chip1608_GS_1" Chip1608_GS_1#2 250.5,36.5 r270 top
R193 "Chip1608_GS_1" Chip1608_GS_1#2 248,38.5 r180 top
R194 "Chip1608_GS_1" Chip1608_GS_1#1 266.5,40 r180 bottom
R195 "Chip1608_GS_1" Chip1608_GS_1#1 266.5,35.2 r180 bottom
R196 "Chip1608_GS_1" Chip1608_GS_1#2 266.5,42.6 r0 top
R197 "Chip1608_GS_1" Chip1608_GS_1#2 266.5,37.8 r0 top
R198 "Chip1608_GS_1" Chip1608_GS_1#2 163.75,29.5 r180 top
R199 "Chip6432_GS" Chip6432_GS#1 327.8,84 r0 bottom
R200 "Chip6432_GS" Chip6432_GS#1 319.65,134.9 r90 bottom
R201 "Chip6432_GS" Chip6432_GS#1 328.9,118 r0 bottom
R204 "Chip1608_GS_1" Chip1608_GS_1#1 328.6,142 r270 bottom
R205 "Chip1608_GS_1" Chip1608_GS_1#1 331.2,27.6 r0 bottom
R206 "Chip1608_GS_1" Chip1608_GS_1#1 330,24.5 r270 bottom
R207 "Chip1608_GS_1" Chip1608_GS_1#2 285.7,37.45 r0 top
R208 "Chip1608_GS_1" Chip1608_GS_1#2 273,32.95 r0 top
R209 "Chip1608_GS_1" Chip1608_GS_1#2 273,34.85 r0 top
R210 "Chip1608_GS_1" Chip1608_GS_1#1 273,30.95 r0 bottom
R211 "Chip1608_GS_1" Chip1608_GS_1#1 273,33.75 r0 bottom
R212 "Chip3216_GS_1" Chip3216_GS_1#1 277.2,133.3 r180 bottom
R213 "Chip3216_GS_1" Chip3216_GS_1#1 283.3,115.25 r180 bottom
R214 "Chip3216_GS_1" Chip3216_GS_1#1 277.2,95.3 r180 bottom
R215 "Chip3216_GS_1" Chip3216_GS_1#1 283.6,72.5 r180 bottom
R220 "Chip1608_GS_1" Chip1608_GS_1#2 149.6,85.2 r90 top
R221 "Chip1608_GS_1" Chip1608_GS_1#2 202.3,86.8 r0 top
R222 "Chip1608_GS_1" Chip1608_GS_1#2 136.3,64.1 r90 top
R223 "Chip1608_GS_1" Chip1608_GS_1#2 204.6,101 r90 top
R224 "Chip1608_GS_1" Chip1608_GS_1#2 206.75,143 r180 top
R225 "Chip1608_GS_1" Chip1608_GS_1#2 103.5,143 r0 top
R227 "Chip1608_GS_1" Chip1608_GS_1#1 171.85,31.55 r90 bottom
R228 "Chip1608_GS_1" Chip1608_GS_1#1 172.25,28.7 r270 bottom
R800 "R_I_MOS3C_KO" R_I_MOS3C_KO 227.8,51 r0 top
R801 "Chip3225_GS_1" Chip3225_GS_1#1 220.8,48.1 r180 bottom
R802 "Chip3216_GS_1" Chip3216_GS_1#1 206.5,53.7 r90 bottom
R803 "Chip1608_GS_1" Chip1608_GS_1#1 208.6,52.7 r90 bottom
R804 "Chip1608_GS_1" Chip1608_GS_1#1 208.6,55.3 r90 bottom
R805 "Chip1608_GS_1" Chip1608_GS_1#1 208.75,21.7 r0 bottom
R806 "Chip3216_GS_1" Chip3216_GS_1#1 199.8,64.35 r180 bottom
R807 "Chip1608_GS_1" Chip1608_GS_1#1 206.4,64.45 r0 bottom
R808 "Chip1608_GS_1" Chip1608_GS_1#1 202.65,66.75 r0 bottom
R809 "Chip1608_GS_1" Chip1608_GS_1#1 205.15,66.75 r0 bottom
R810 "Chip1608_GS_1" Chip1608_GS_1#2 207.2,60.2 r270 top
R811 "Chip1608_GS_1" Chip1608_GS_1#2 207.2,57.55 r270 top
R812 "Chip3216_GS_1" Chip3216_GS_1#1 213.55,51.9 r0 bottom
R813 "Chip3216_GS_1" Chip3216_GS_1#1 213.55,54.15 r0 bottom
R814 "Chip3216_GS_1" Chip3216_GS_1#1 213.55,56.4 r0 bottom
R820 "Chip3216_GS_1" Chip3216_GS_1#1 265.9,22.4 r180 bottom
RV1 "ZD_I_TND14V-561_CC" ZD_I_TND14V-561_CC 57.7,43.5 r0 top
T2 "T_I_P009-203_PO" T_I_P009-203_PO 158.1,87.8 r270 top
T3 "T_I_P009-203_PO" T_I_P009-203_PO 134.6,87.8 r270 top
T4 "T_I_PE-63587NL_PU" T_I_PE-63587NL_PU 254,54.65 r0 top
T5 "T_I_AN0545_GS" T_I_AN0545_GS 241.5,88.9 r0 top
T6 "T_I_AN0545_GS" T_I_AN0545_GS 241.5,127.5 r0 top
T8 "T_I_WT2020_GS" T_I_WT2020_GS 227.25,34.4 r270 top
TP1 "TP_S_HK-2_M8" TP_S_HK-2_M8 143.9,97.5 r0 top
TP2 "TP_S_HK-2_M8" TP_S_HK-2_M8 129.2,97.5 r0 top
TP3 "TP_S_HK-2_M8" TP_S_HK-2_M8 176.05,61.5 r0 top
TP4 "TP_S_HK-2_M8" TP_S_HK-2_M8 144.8,83.9 r0 top
TP5 "TP_S_HK-2_M8" TP_S_HK-2_M8 161.15,21.6 r0 top
TP6 "TP_S_HK-2_M8" TP_S_HK-2_M8 154.05,21.6 r0 top
TP7 "TP_S_HK-2_M8" TP_S_HK-2_M8 168.05,21.6 r0 top
TP8 "TP_S_HK-2_M8" TP_S_HK-2_M8 174.35,21.6 r0 top
TP9 "TP_S_HK-2_M8" TP_S_HK-2_M8 177.9,83 r0 top
TP10 "TP_S_HK-2_M8" TP_S_HK-2_M8 172.5,84 r0 top
TP11 "TP_S_HK-2_M8" TP_S_HK-2_M8 172.5,108.6 r0 top
TP12 "TP_S_HK-2_M8" TP_S_HK-2_M8 179.5,108.6 r0 top
TP15 "TP_S_HK-2_M8" TP_S_HK-2_M8 191.8,137.3 r0 top
TP17 "TP_S_HK-2_M8" TP_S_HK-2_M8 266.3,110.45 r0 top
TP18 "TP_S_HK-2_M8" TP_S_HK-2_M8 266.3,72.4 r0 top
TP19 "TP_S_HK-2_M8" TP_S_HK-2_M8 285.25,131.05 r270 top
TP20 "TP_S_HK-2_M8" TP_S_HK-2_M8 292.35,95 r0 top
TP21 "TP_S_HK-2_M8" TP_S_HK-2_M8 275.65,134.35 r0 top
TP22 "TP_S_HK-2_M8" TP_S_HK-2_M8 275.35,96.4 r0 top
TP24 "TP_S_HK-2_M8" TP_S_HK-2_M8 285.25,123.4 r90 top
TP25 "TP_S_HK-2_M8" TP_S_HK-2_M8 290.95,83.35 r0 top
TP28 "TP_S_HK-2_M8" TP_S_HK-2_M8 308.75,41.75 r90 top
TP29 "TP_S_HK-2_M8" TP_S_HK-2_M8 266.3,124.6 r0 top
TP30 "TP_S_HK-2_M8" TP_S_HK-2_M8 266.35,145.4 r0 top
TP31 "TP_S_HK-2_M8" TP_S_HK-2_M8 326.9,80.75 r180 top
TP38 "TP_S_HK-2_M8" TP_S_HK-2_M8 158.4,135.4 r0 top
TP39 "TP_S_HK-2_M8" TP_S_HK-2_M8 152.1,135.4 r0 top
TP41 "TP_I_LC-22_GS" TP_I_LC-22_GS 335,133.1 r0 top
TP42 "TP_I_LC-22_GS" TP_I_LC-22_GS 296.7,28 r0 top
TP43 "TP_I_LC-22_GS" TP_I_LC-22_GS 142,22 r0 top
TP44 "TP_S_HK-2_M8" TP_S_HK-2_M8 180.95,22.4 r90 top
TP45 "TP_I_LC-22_GS" TP_I_LC-22_GS 186.7,22 r0 top
TP80 "TP_S_HK-2_M8" TP_S_HK-2_M8 200.05,41.8 r180 top
TP81 "TP_S_HK-2_M8" TP_S_HK-2_M8 297,33.2 r0 top
TP82 "TP_S_HK-2_M8" TP_S_HK-2_M8 194.85,60.55 r90 top

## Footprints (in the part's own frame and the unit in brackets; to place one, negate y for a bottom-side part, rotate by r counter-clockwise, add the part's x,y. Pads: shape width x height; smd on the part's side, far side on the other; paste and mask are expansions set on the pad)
AC_I_DIA-8_CC_1 [mm] "KC00080BKP"
  round 1.5 hole 0.85 paste-1.6 mask+0: 1(1.75,0) 2(-1.75,0)
  silkscreen extent -5.5,-4 4,4
AC_I_DIA-10_CC [mm] "KC00080BKP"
  round 1.5 hole 0.85 paste-1.6 mask+0: 1(2.5,0) 2(-2.5,0)
  silkscreen extent -6.1,-5 5,5
AC_I_DIA-10_CC_2 [mm] "KC00080BKP"
  round 1.5 hole 0.85 paste-1.6 mask+0: 1(2.5,0) 2(-2.5,0)
  silkscreen extent -6.1,-5 5,5
AC_I_DIA-10_CC_3 [mm] "KC00080BKP"
  round 1.5 hole 0.85 paste-1.6 mask+0: 1(2.5,0) 2(-2.5,0)
  silkscreen extent -6.1,-5 5,5
AC_I_DIA-30_RB [mm] "KC00080BKP"
  round 3.5 hole 2 paste-3.6 mask+0: 1(5,0) 2(-5,0)
  silkscreen extent -15.25,-15.25 15.25,15.25
C_I_890324026034CS_WE [mm] "KC00080BKP"
  round 1.7 hole 1.1 paste-1.8 mask+0: 1(-11.25,0) 2(11.25,0)
  silkscreen extent -13,-7.5 13,7.5
C_I_DE1B3RA471_GS_1 [mm] "KC00080BKP"
  round 1.45 hole 0.85 paste-1.55 mask+0: 1(-3.75,0) 2(3.75,0)
  silkscreen extent -3.5,-2 3.5,3.75
C_I_DE2**KY*******M**F_MU [mm] "KC00080BKP"
  round 1.45 hole 0.85 paste-1.55 mask+0: 1(-3.75,0) 2(3.75,0)
  silkscreen extent -3.5,-2.5 3.5,2.5
C_I_DE2**KY*******M**F_MU_2 [mm] "KC00080BKP"
  round 1.45 hole 0.85 paste-1.55 mask+0: 1(-3.75,0) 2(3.75,0)
  silkscreen extent -4,-2.5 4,2.5
C_I_LE224-M_OK [mm] "KC00080BKP"
  round 1.45 hole 0.85 paste-1.55 mask+0: 1(-6.25,0) 2(6.25,0)
  silkscreen extent -7,-4.25 7,4.25
C_I_LE474-M_OK [mm] "KC00080BKP"
  round 1.5 hole 0.85 paste-1.6 mask+0: 1(-7.5,0) 2(7.5,0)
  silkscreen extent -8.5,-5.75 8.5,5.75
C_I_RDER72J104_MU [mm] "KC00080BKP"
  round 1.4 hole 0.8 paste-1.5 mask+0: 1(-2.5,0) 2(2.5,0)
  silkscreen extent -3.75,-2 3.75,2
Chip1005_GS_2#1 [mm] "KC00080BKP"
  rect 0.45x0.5 smd paste-0.6 mask+0: 1(-0.475,0) 2(0.475,0)
  silkscreen extent 0,-0.2 0,0.2
Chip1005_GS_2#2 [mm] "KC00080BKP"
  rect 0.45x0.5 smd paste-0.6 mask+0: 1(0.475,0) 2(-0.475,0)
  silkscreen extent 0,-0.2 0,0.2
Chip1608_GS_1#1 [mm] "KC00080BKP"
  rect 0.7x0.8 smd paste-0.9 mask+0: 1(0.7,0) 2(-0.7,0)
  silkscreen extent 0,-0.35 0,0.35
Chip1608_GS_1#2 [mm] "KC00080BKP"
  rect 0.7x0.8 smd paste-0.9 mask+0: 1(-0.7,0) 2(0.7,0)
  silkscreen extent 0,-0.35 0,0.35
Chip2012_GS_1#1 [mm] "KC00080BKP"
  rect 0.7x1.3 smd paste-1.4 mask+0: 1(0.95,0) 2(-0.95,0)
  silkscreen extent 0,-0.63 0,0.63
Chip2012_GS_1#2 [mm] "KC00080BKP"
  rect 0.7x1.3 smd paste-1.4 mask+0: 1(-0.95,0) 2(0.95,0)
  silkscreen extent 0,-0.63 0,0.63
Chip3216_GS_1#1 [mm] "KC00080BKP"
  rect 1x1.6 smd paste-1.7 mask+0: 1(1.6,0) 2(-1.6,0)
  silkscreen extent -0.85,-0.75 0.85,0.75
Chip3216_GS_1#2 [mm] "KC00080BKP"
  rect 1x1.6 smd paste-1.7 mask+0: 1(-1.6,0) 2(1.6,0)
  silkscreen extent -0.85,-0.75 0.85,0.75
Chip3225_GS_1#1 [mm] "KC00080BKP"
  rect 1.1x2.2 smd paste-2.3 mask+0: 1(1.65,0) 2(-1.65,0)
  silkscreen extent -0.9,-1.25 0.9,1.25
Chip3225_GS_1#2 [mm] "KC00080BKP"
  rect 1.1x2.2 smd paste-2.3 mask+0: 1(-1.65,0) 2(1.65,0)
  silkscreen extent -0.9,-1.25 0.9,1.25
Chip6432_GS#1 [mm] "KC00080BKP"
  rect 1.7x3.2 smd paste-3.3 mask+0: 1(3.15,0) 2(-3.15,0)
  silkscreen extent -2.05,-1.6 2.05,1.6
Chip6432_GS#2 [mm] "KC00080BKP"
  rect 1.7x3.2 smd paste-3.3 mask+0: 1(-3.15,0) 2(3.15,0)
  silkscreen extent -2.05,-1.6 2.05,1.6
CN_I_5045-02A_MX [mm] "KC00080BKP"
  round 1.8 hole 1.2 paste-1.9 mask+0: 1(1.25,0) 2(-1.25,0)
  silkscreen extent -2.25,-3.2 2.25,2.6
DI_I_GSIB-5S_4_VS [mm] "KC00080BKP"
  round 2.6 hole 1.6 paste-2.7 mask+0: 1(-12.5,0) 2(-2.5,0) 3(5,0) 4(12.5,0)
  silkscreen extent -15,-1.55 15,3.05
DI_I_TO220-2_KC [mm] "KC00080BKP"
  round 1.8 hole 1.15 paste-1.9 mask+0: A(2.55,0) C(-2.55,0)
  silkscreen extent -5.05,-1.5 5.05,3
DI_I_TO220F-2L_TS [mm] "KC00080BKP"
  round 1.8 hole 1.2 paste-1.9 mask+0: A(2.54,0) C(-2.54,0)
  silkscreen extent -5,-1.62 5,2.88
DI_S_1SS387_TS_B [mm] "KC00080BKP"
  rect 0.8x0.6 smd paste-0.9 mask+0: A(0,-0.85) C(0,0.85)
  silkscreen extent -0.85,-0.45 0.85,0.45
DI_S_3-2A1S_2_TS_A#1 [mm] "KC00080BKP"
  rect 1.2x1.2 smd paste-1.2 mask+0: A(-1.4,0) C(1.4,0)
  round 0 all layers, no hole paste-1.3 mask+0: ""(-1.4,0) ""(1.4,0)
  silkscreen extent -1.3,-1.25 1.3,1.25
DI_S_3-2A1S_2_TS_A#2 [mm] "KC00080BKP"
  rect 1.2x1.2 smd paste-1.2 mask+0: A(1.4,0) C(-1.4,0)
  round 0 all layers, no hole paste-1.3 mask+0: ""(-1.4,0) ""(1.4,0)
  silkscreen extent -1.3,-1.25 1.3,1.25
DI_S_3-4E1A_2_TS_B [mm] "KC00080BKP"
  rect 1.4x2.1 smd paste-2.2 mask+0: A(2.2,0) C(-2.2,0)
  silkscreen extent -1.9,-1.8 1.9,1.8
DI_S_CRS01_TS_B#1 [mm] "KC00080BKP"
  rect 1.2x1.2 smd paste-1.3 mask+0: A(-1.4,0) C(1.4,0)
  silkscreen extent -1.3,-1.1 1.3,1.25
DI_S_CRS01_TS_B#2 [mm] "KC00080BKP"
  rect 1.2x1.2 smd paste-1.3 mask+0: A(1.4,0) C(-1.4,0)
  silkscreen extent -1.3,-1.25 1.3,1.25
DI_S_SOD-123_2_OS_A [mm] "KC00080BKP"
  rect 0.9x1.2 smd paste-1.3 mask+0: A(-1.63,0) C(1.63,0)
  silkscreen extent -1.35,-1.2 1.35,1.15
DI_S_SOT23_3_0.95_TS_B#1 [mm] "KC00080BKP"
  rect 0.6x0.7 smd paste-0.8 mask+0: A(0.95,1) C(0,-1) NC(-0.95,1)
  silkscreen extent -1.45,-0.65 1.45,0.65
DI_S_SOT23_3_0.95_TS_B#2 [mm] "KC00080BKP"
  rect 0.6x0.7 smd paste-0.8 mask+0: A(-0.95,-1) C(0,1) NC(0.95,-1)
  silkscreen extent -1.45,-0.65 1.45,0.65
DI_S_USC_2_TS_B#1 [mm] "KC00080BKP"
  rect 0.8x0.9 smd paste-1 mask+0: A(-1.15,0) C(1.15,0)
  silkscreen extent -0.6,-0.88 0.55,0.87
DI_S_USC_2_TS_B#2 [mm] "KC00080BKP"
  rect 0.8x0.9 smd paste-1 mask+0: A(1.15,0) C(-1.15,0)
  silkscreen extent -0.55,-0.87 0.6,0.87
Drawing-Flame_4x120 [mm] "KC00080BKP"
F_I_808****0440_LF [mm] "KC00080BKP"
  round 1.5 hole 0.85 paste-1.6 mask+0: 1(-2.54,0) 2(2.54,0)
  silkscreen extent -4.45,-2.33 4.45,2.32
F_I_02150***XEP_LF [mm] "KC00080BKP"
  round 2.5 hole 1.5 paste-2.6 mask+0: 1(0,0) 2(10,0)
  silkscreen extent -2.75,-2.75 8.6,2.75
F_I_A5MC_UC [mm] "KC00080BKP"
  round 1.5 hole 0.85 paste-1.6 mask+0: 1(-2.75,0)
  round 1.7 hole 1.05 paste-1.8 mask+0: 2(2.75,0)
  silkscreen extent -7.25,-4.5 6.75,4.5
FB_S_FBMH3216_TY [mm] "KC00080BKP"
  rect 1.4x2 smd paste-2.1 mask+0: 1(-1.8,0) 2(1.8,0)
  silkscreen extent -0.85,-0.8 0.85,0.8
FiducialMark_add_withM#1 [mm] "KC00080BKP"
  round 1 / inner round 0 / far side round 1 all layers, no hole paste-2 mask+0: ""(0,0)
  round 1 / inner round 0 / far side round 1 all layers, no hole paste-1 mask+0: ""(2,0)
FiducialMark_add_withM#2 [mm] "KC00080BKP"
  round 1 / inner round 0 / far side round 1 all layers, no hole paste-2 mask+0: ""(-12,0)
  round 1 / inner round 0 / far side round 1 all layers, no hole paste-1 mask+0: ""(-10,0)
HP_I_A2-2PA-2.54DSA_HR [mm] "KC00080BKP"
  round 1.5 hole 0.85 paste-1.6 mask+0: 1(-1.27,0) 2(1.27,0)
  silkscreen extent -2.39,-1.27 2.39,1.27
HS_I_BPUS15-25_GS [mm] "KC00080BKP"
  round 2.8 / inner round 0 / far side round 2.8 hole 1.8 paste-2.9 mask+0: 1(0,2.9)
  silkscreen extent -7.5,-5 7.5,6
IC_S_SOP_5_0.65_TS_1#1 [mm] "KC00080BKP"
  rect 0.4x0.8 smd paste-0.9 mask+0: 1(0.65,0.95) 2(0,0.95) 3(-0.65,0.95) 4(-0.65,-0.95) 5(0.65,-0.95)
  silkscreen extent -1,-0.63 1,0.35
IC_S_SOP_5_0.65_TS_1#2 [mm] "KC00080BKP"
  rect 0.4x0.8 smd paste-0.9 mask+0: 1(-0.65,-0.95) 2(0,-0.95) 3(0.65,-0.95) 4(0.65,0.95) 5(-0.65,0.95)
  silkscreen extent -1,-0.35 1,0.63
IC_S_SOP_5_0.95_TI [mm] "KC00080BKP"
  rect 0.6x1.05 smd paste-1.15 mask+0: 1(0.95,1.35) 2(0,1.35) 3(-0.95,1.35) 4(-0.95,-1.35) 5(0.95,-1.35)
  silkscreen extent -1.45,-0.8 1.45,0.55
IC_S_SOP_6_0.95_TI [mm] "KC00080BKP"
  rect 0.6x1.1 smd paste-1.2 mask+0: 1(0.95,1.3) 2(0,1.3) 3(-0.95,1.3) 4(-0.95,-1.3) 5(0,-1.3) 6(0.95,-1.3)
  silkscreen extent -1.45,-0.55 1.45,0.55
IC_S_SOP_7_1.27_TI [mm] "KC00080BKP"
  rect 0.6x1.55 smd paste-1.65 mask+0: CS(-1.905,-2.7) DRV(-0.635,-2.7) GND(-1.905,2.7) HV(1.905,-2.7) NTC(-0.635,2.7) VDD(1.905,2.7) VS(0.635,2.7)
  silkscreen extent -2.45,-1.65 2.45,1.65
IC_S_SOP_8_1.27_MPS [mm] "KC00080BKP"
  rect 0.6x1.6 smd paste-1.7 mask+0: 1(1.905,2.7) 2(0.635,2.7) 3(-0.635,2.7) 4(-1.905,2.7) 5(-1.905,-2.7) 6(-0.635,-2.7) 7(0.635,-2.7) 8(1.905,-2.7)
  silkscreen extent -2.45,-1.65 2.45,1.65
IC_S_SOP_8_1.27_TI [mm] "KC00080BKP"
  rect 0.6x1.55 smd paste-1.65 mask+0: 1(-1.905,-2.7) 2(-0.635,-2.7) 3(0.635,-2.7) 4(1.905,-2.7) 5(1.905,2.7) 6(0.635,2.7) 7(-0.635,2.7) 8(-1.905,2.7)
  silkscreen extent -2.45,-1.65 2.45,1.65
IC_S_SOP_14_1.27_TI [mm] "KC00080BKP"
  rect 0.6x1.55 smd paste-1.65 mask+0: 1(-3.81,-2.7) 2(-2.54,-2.7) 3(-1.27,-2.7) 4(0,-2.7) 5(1.27,-2.7) 6(2.54,-2.7) 7(3.81,-2.7) 8(3.81,2.7) 9(2.54,2.7) 10(1.27,2.7) 11(0,2.7) 12(-1.27,2.7) 13(-2.54,2.7) 14(-3.81,2.7)
  silkscreen extent -4.33,-1.65 4.32,1.65
IC_S_SOP_20_0.65_TI [mm] "KC00080BKP"
  rect 0.3x1.6 smd paste-1.7 mask+0: 1(2.925,2.8) 2(2.275,2.8) 3(1.625,2.8) 4(0.975,2.8) 5(0.325,2.8) 6(-0.325,2.8) 7(-0.975,2.8) 8(-1.625,2.8) 9(-2.275,2.8) 10(-2.925,2.8) 11(-2.925,-2.8) 12(-2.275,-2.8) 13(-1.625,-2.8) 14(-0.975,-2.8) 15(-0.325,-2.8) 16(0.325,-2.8) 17(0.975,-2.8) 18(1.625,-2.8) 19(2.275,-2.8) 20(2.925,-2.8)
  silkscreen extent -3.25,-1.75 3.25,1.75
IC_S_SOP_24_0.65_GS_1 [mm] "KC00080BKP"
  rect 0.4x1.5 smd paste-1.6 mask+0: 1(3.575,2.9) 2(2.925,2.9) 3(2.275,2.9) 4(1.625,2.9) 5(0.975,2.9) 6(0.325,2.9) 7(-0.325,2.9) 8(-0.975,2.9) 9(-1.625,2.9) 10(-2.275,2.9) 11(-2.925,2.9) 12(-3.575,2.9) 13(-3.575,-2.9) 14(-2.925,-2.9) 15(-2.275,-2.9) 16(-1.625,-2.9) 17(-0.975,-2.9) 18(-0.325,-2.9) 19(0.325,-2.9) 20(0.975,-2.9) 21(1.625,-2.9) 22(2.275,-2.9) 23(2.925,-2.9) 24(3.575,-2.9)
  silkscreen extent -3.9,-1.9 3.9,1.9
IC_S_SOT223_3_2.3_TI [mm] "KC00080BKP"
  rect 0.95x2.15 smd paste-2.25 mask+0: ADJ(-2.3,0) IN(2.3,0) OUT_0(0,0)
  rect 3.25x2.15 smd paste-3.35 mask+0: OUT_1(0,5.8)
  silkscreen extent -3.25,1.15 3.25,4.65
L_I_AG1391_GS [mm] "KC00080BKP"
  oval 7.3x2.5 hole 1.4 slot 6.2 at 0 deg paste-7.4 mask+0: 1(8,-15) 2(-8,15)
  silkscreen extent -16,-13.4 16,13.4
L_I_NPA080-13x2-20T_GS [mm] "KC00080BKP"
  oval 5x3.2 hole 1.7 slot 3.5 at 0 deg paste-5.1 mask+0: 1(0,-5) 2(0,5)
  silkscreen extent -13.75,-5 13.75,5
L_I_SCF27-10-1300_TN [mm] "KC00080BKP"
  round 2.6 hole 1.6 paste-2.7 mask+0: 1(-12,10) 2(-12,-10) 3(12,-10) 4(12,10)
  silkscreen extent -17.5,-12 17.5,12
L_I_TH23/14V-08231_TP [mm] "KC00080BKP"
  round 2.5 hole 1.5 paste-2.6 mask+0: 1(0,-10.5) 2(0,10.5)
  silkscreen extent -15,-11 15,11
Logo_TOSHIBA-A [mm] "KC00080BKP"
PCB-Name_4x70 [mm] "KC00080BKP"
PH_S_TLP2767_TS#1 [mm] "KC00080BKP"
  rect 0.8x1.3 smd paste-1.4 mask+0: 1(1.27,4.75) 2(0,4.75) 3(-1.27,4.75) 4(-1.27,-4.75) 5(0,-4.75) 6(1.27,-4.75)
  silkscreen extent -1.92,-3.75 1.92,3.75
PH_S_TLP2767_TS#2 [mm] "KC00080BKP"
  rect 0.8x1.3 smd paste-1.4 mask+0: 1(-1.27,-4.75) 2(0,-4.75) 3(1.27,-4.75) 4(1.27,4.75) 5(0,4.75) 6(-1.27,4.75)
  silkscreen extent -1.92,-3.75 1.92,3.75
R_I_MOS3C_KO [mm] "KC00080BKP"
  round 2 hole 1 paste-2.1 mask+0: 1(0,0) 2(10,0)
  silkscreen extent -3,-3 8.8,3
RE_I_ALKG*2**_PN [mm] "KC00080BKP"
  round 1.5 hole 0.9 paste-1.6 mask+0: 1(-10.35,3.75) 2(-10.35,-3.75)
  round 2.2 hole 1.3 paste-2.3 mask+0: 3(6.15,-3.75) 4(9.65,3.75)
  silkscreen extent -12,-5.5 12,5.5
